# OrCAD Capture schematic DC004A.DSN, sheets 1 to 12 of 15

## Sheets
1 PAGE15 - HARDWARE: size B; title: ADC12DJ3200EVMCVAL (Hardware); rev: A; note: DC004
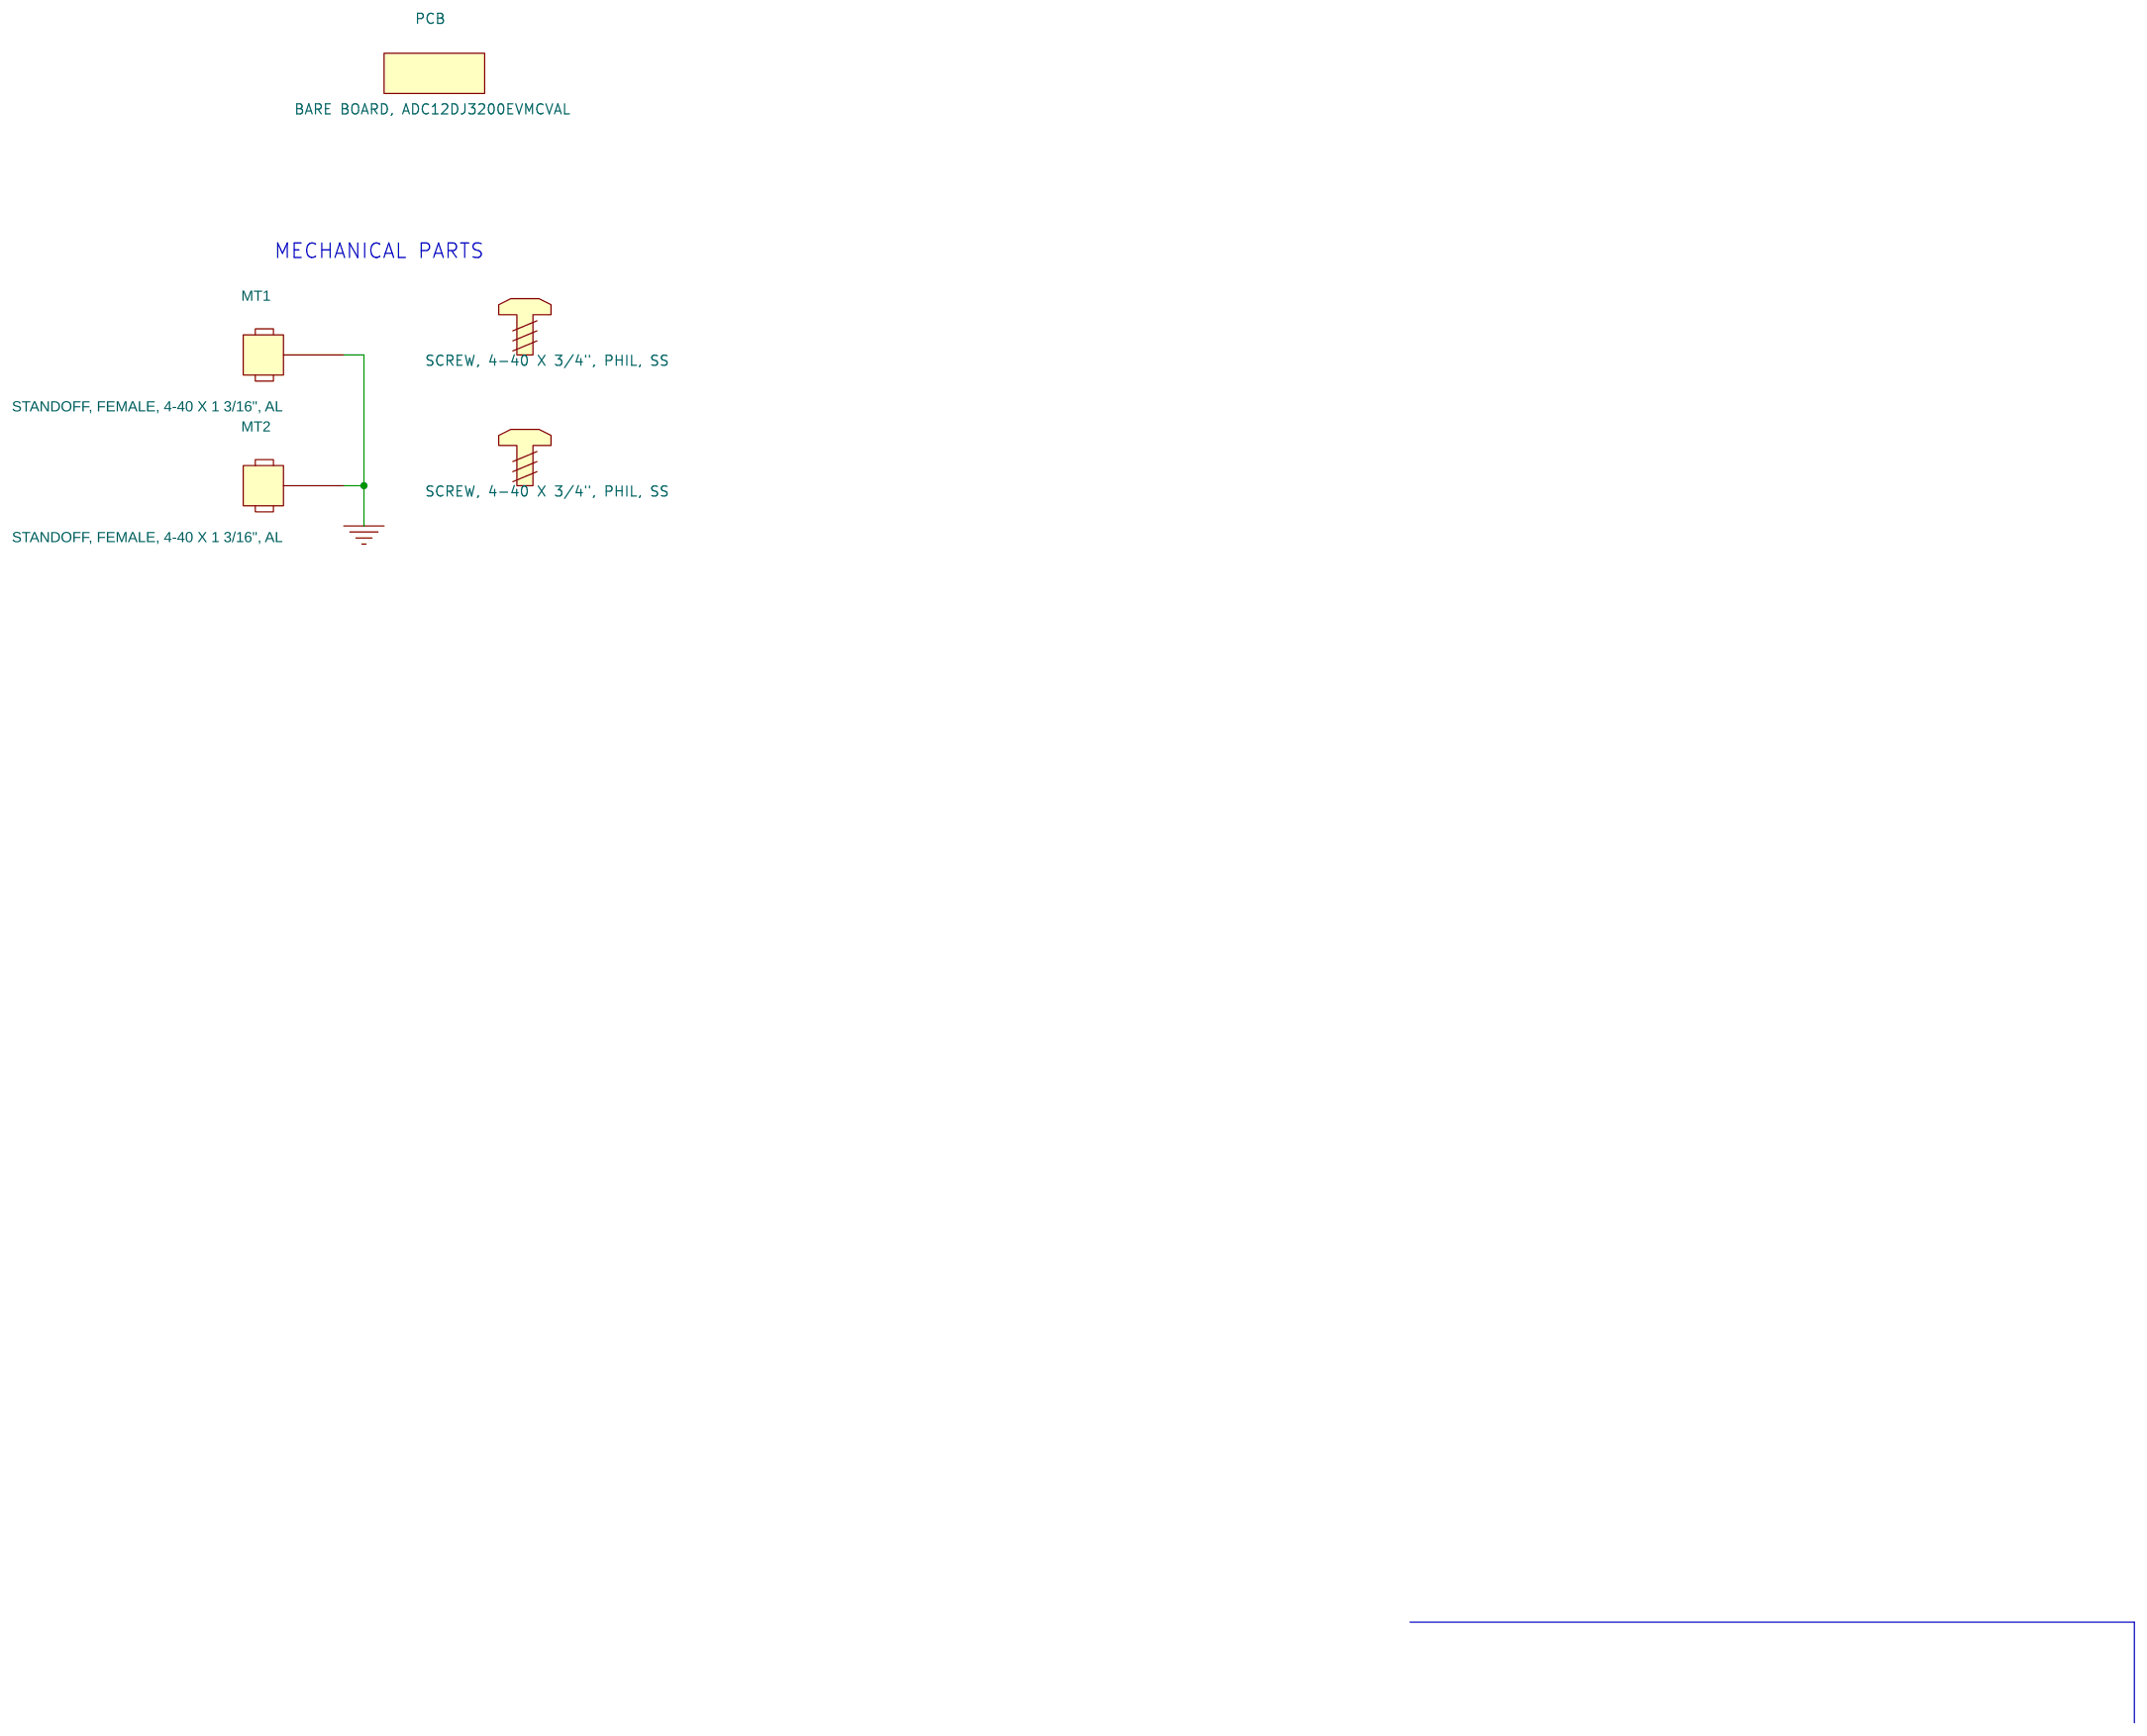
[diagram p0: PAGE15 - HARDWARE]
2 PAGE01 - BLOCK DIAGRAM: title: ADC12DJ3200EVMCVAL
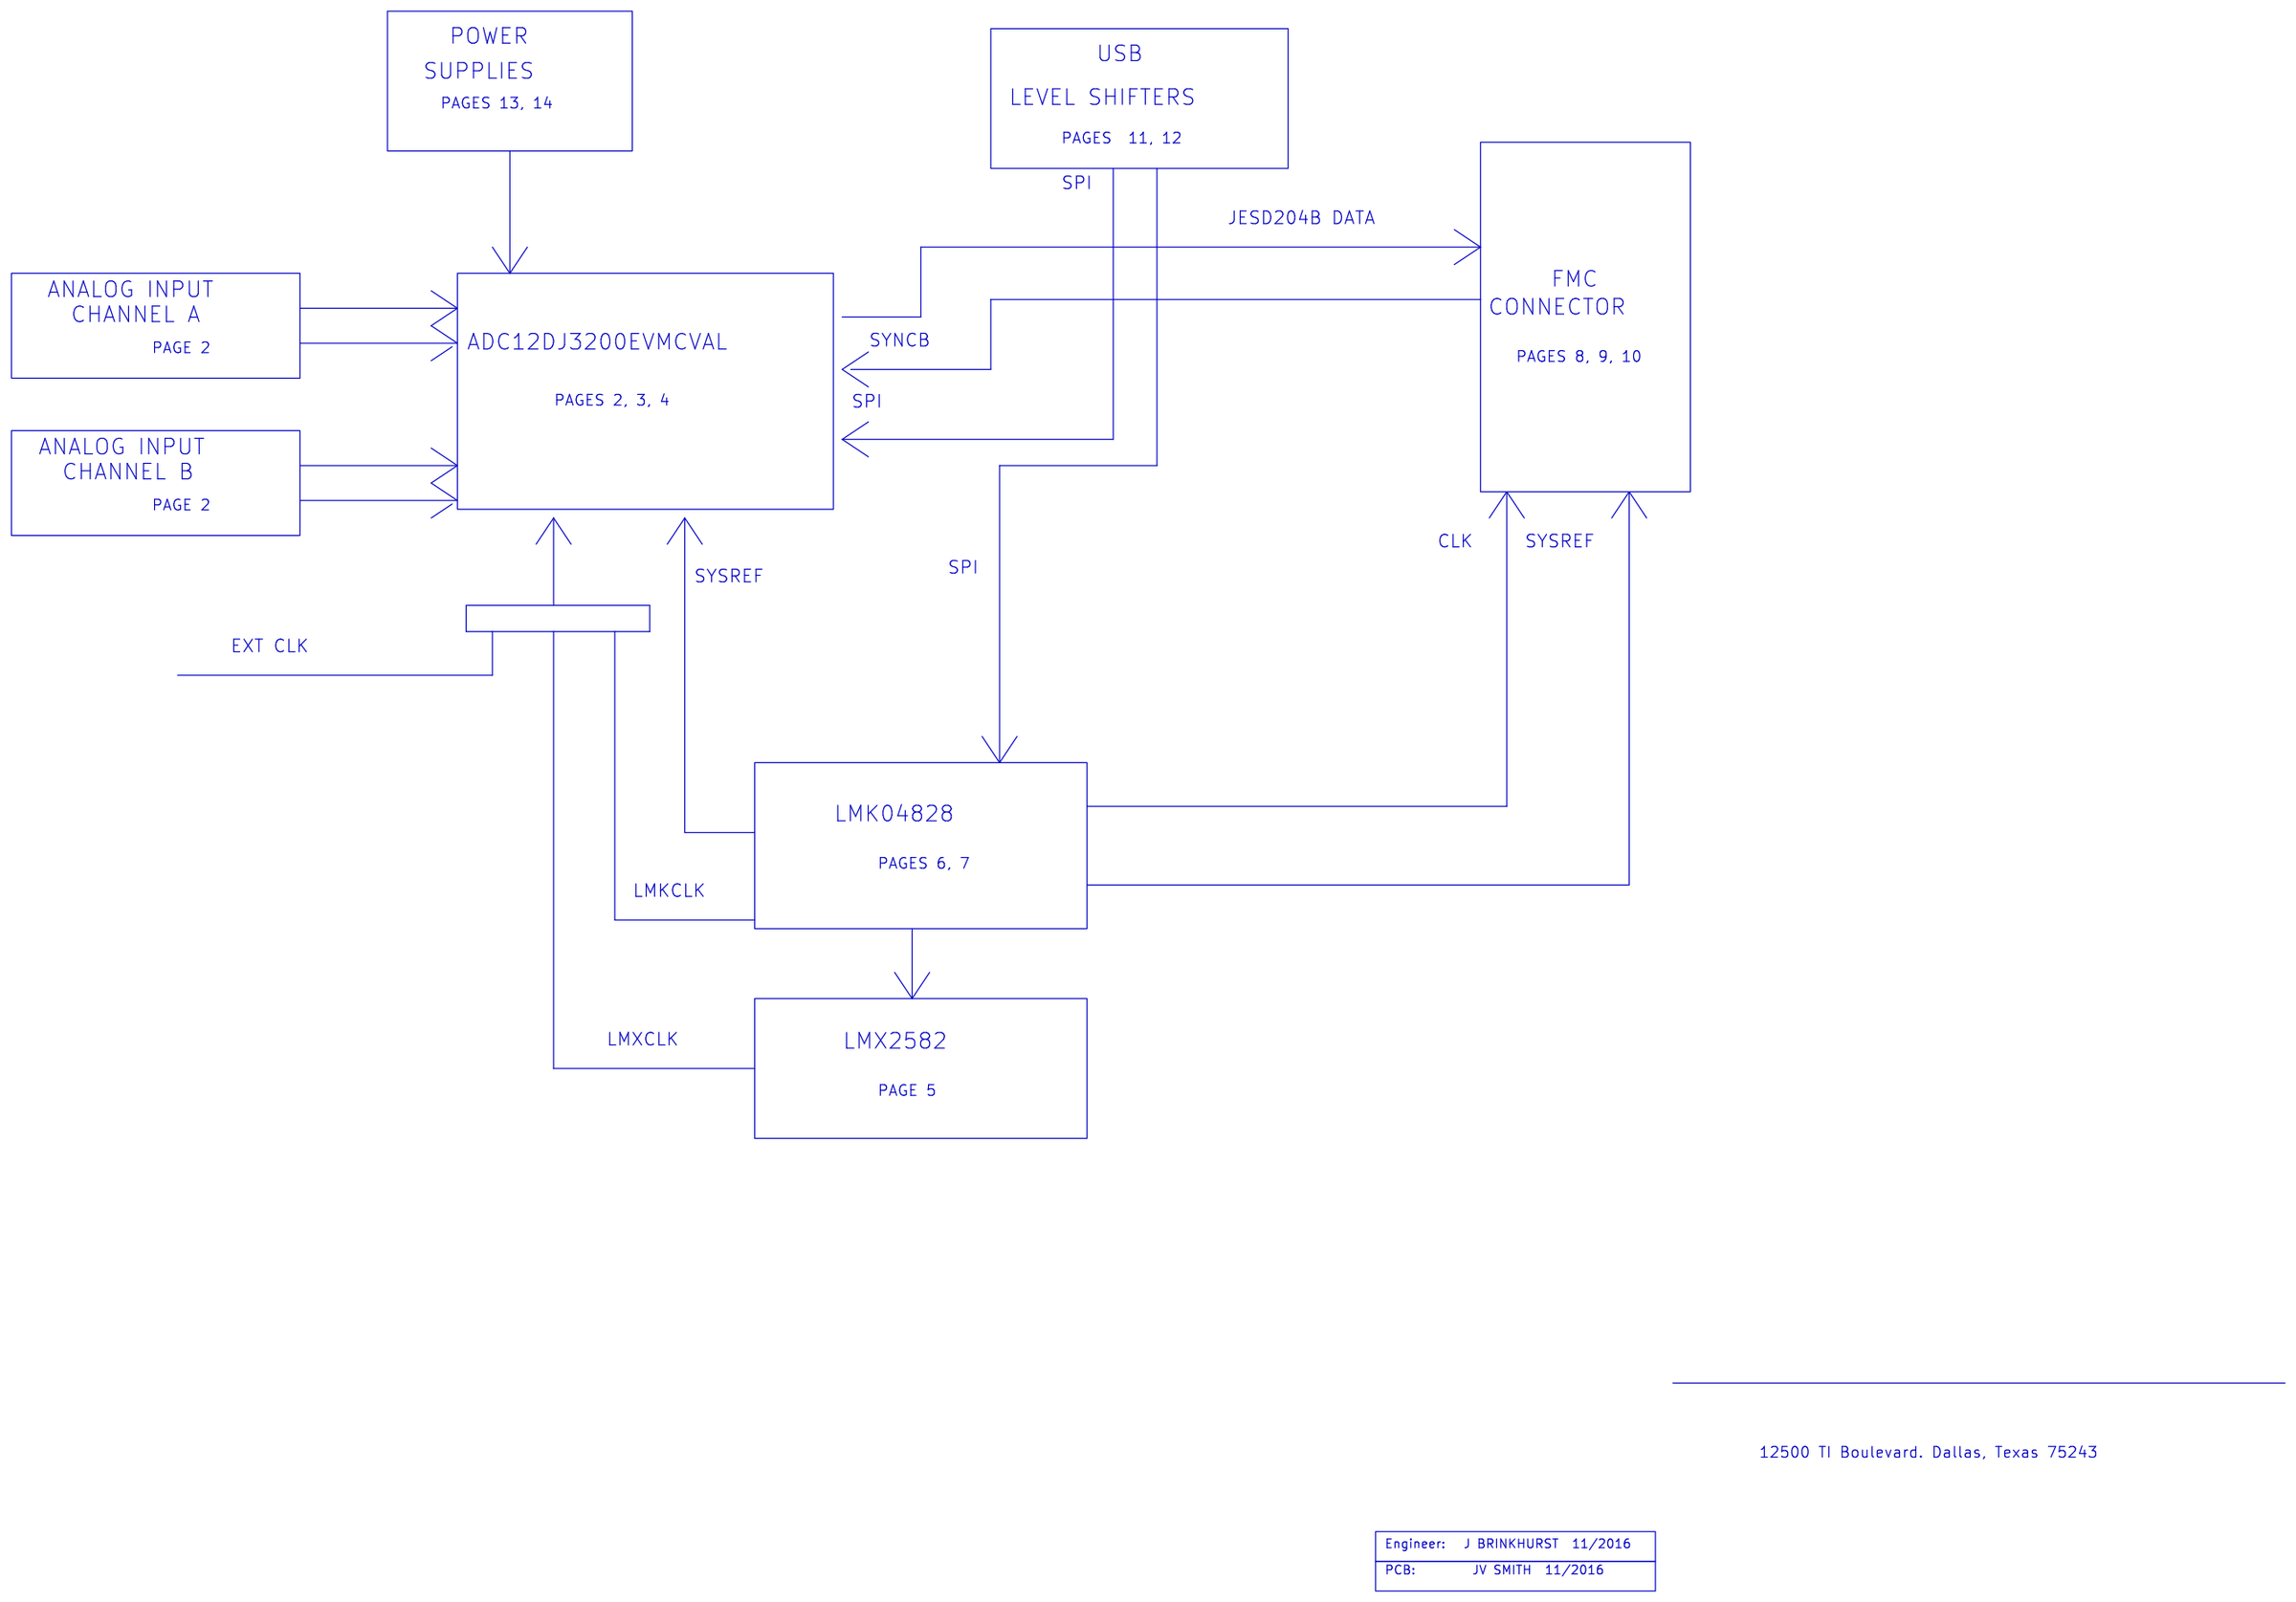
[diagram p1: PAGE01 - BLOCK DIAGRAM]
3 PAGE02 - ADC ANALOG INPUT: size B; title: ADC12DJ3200EVMCVAL (ANALOG INPUT)
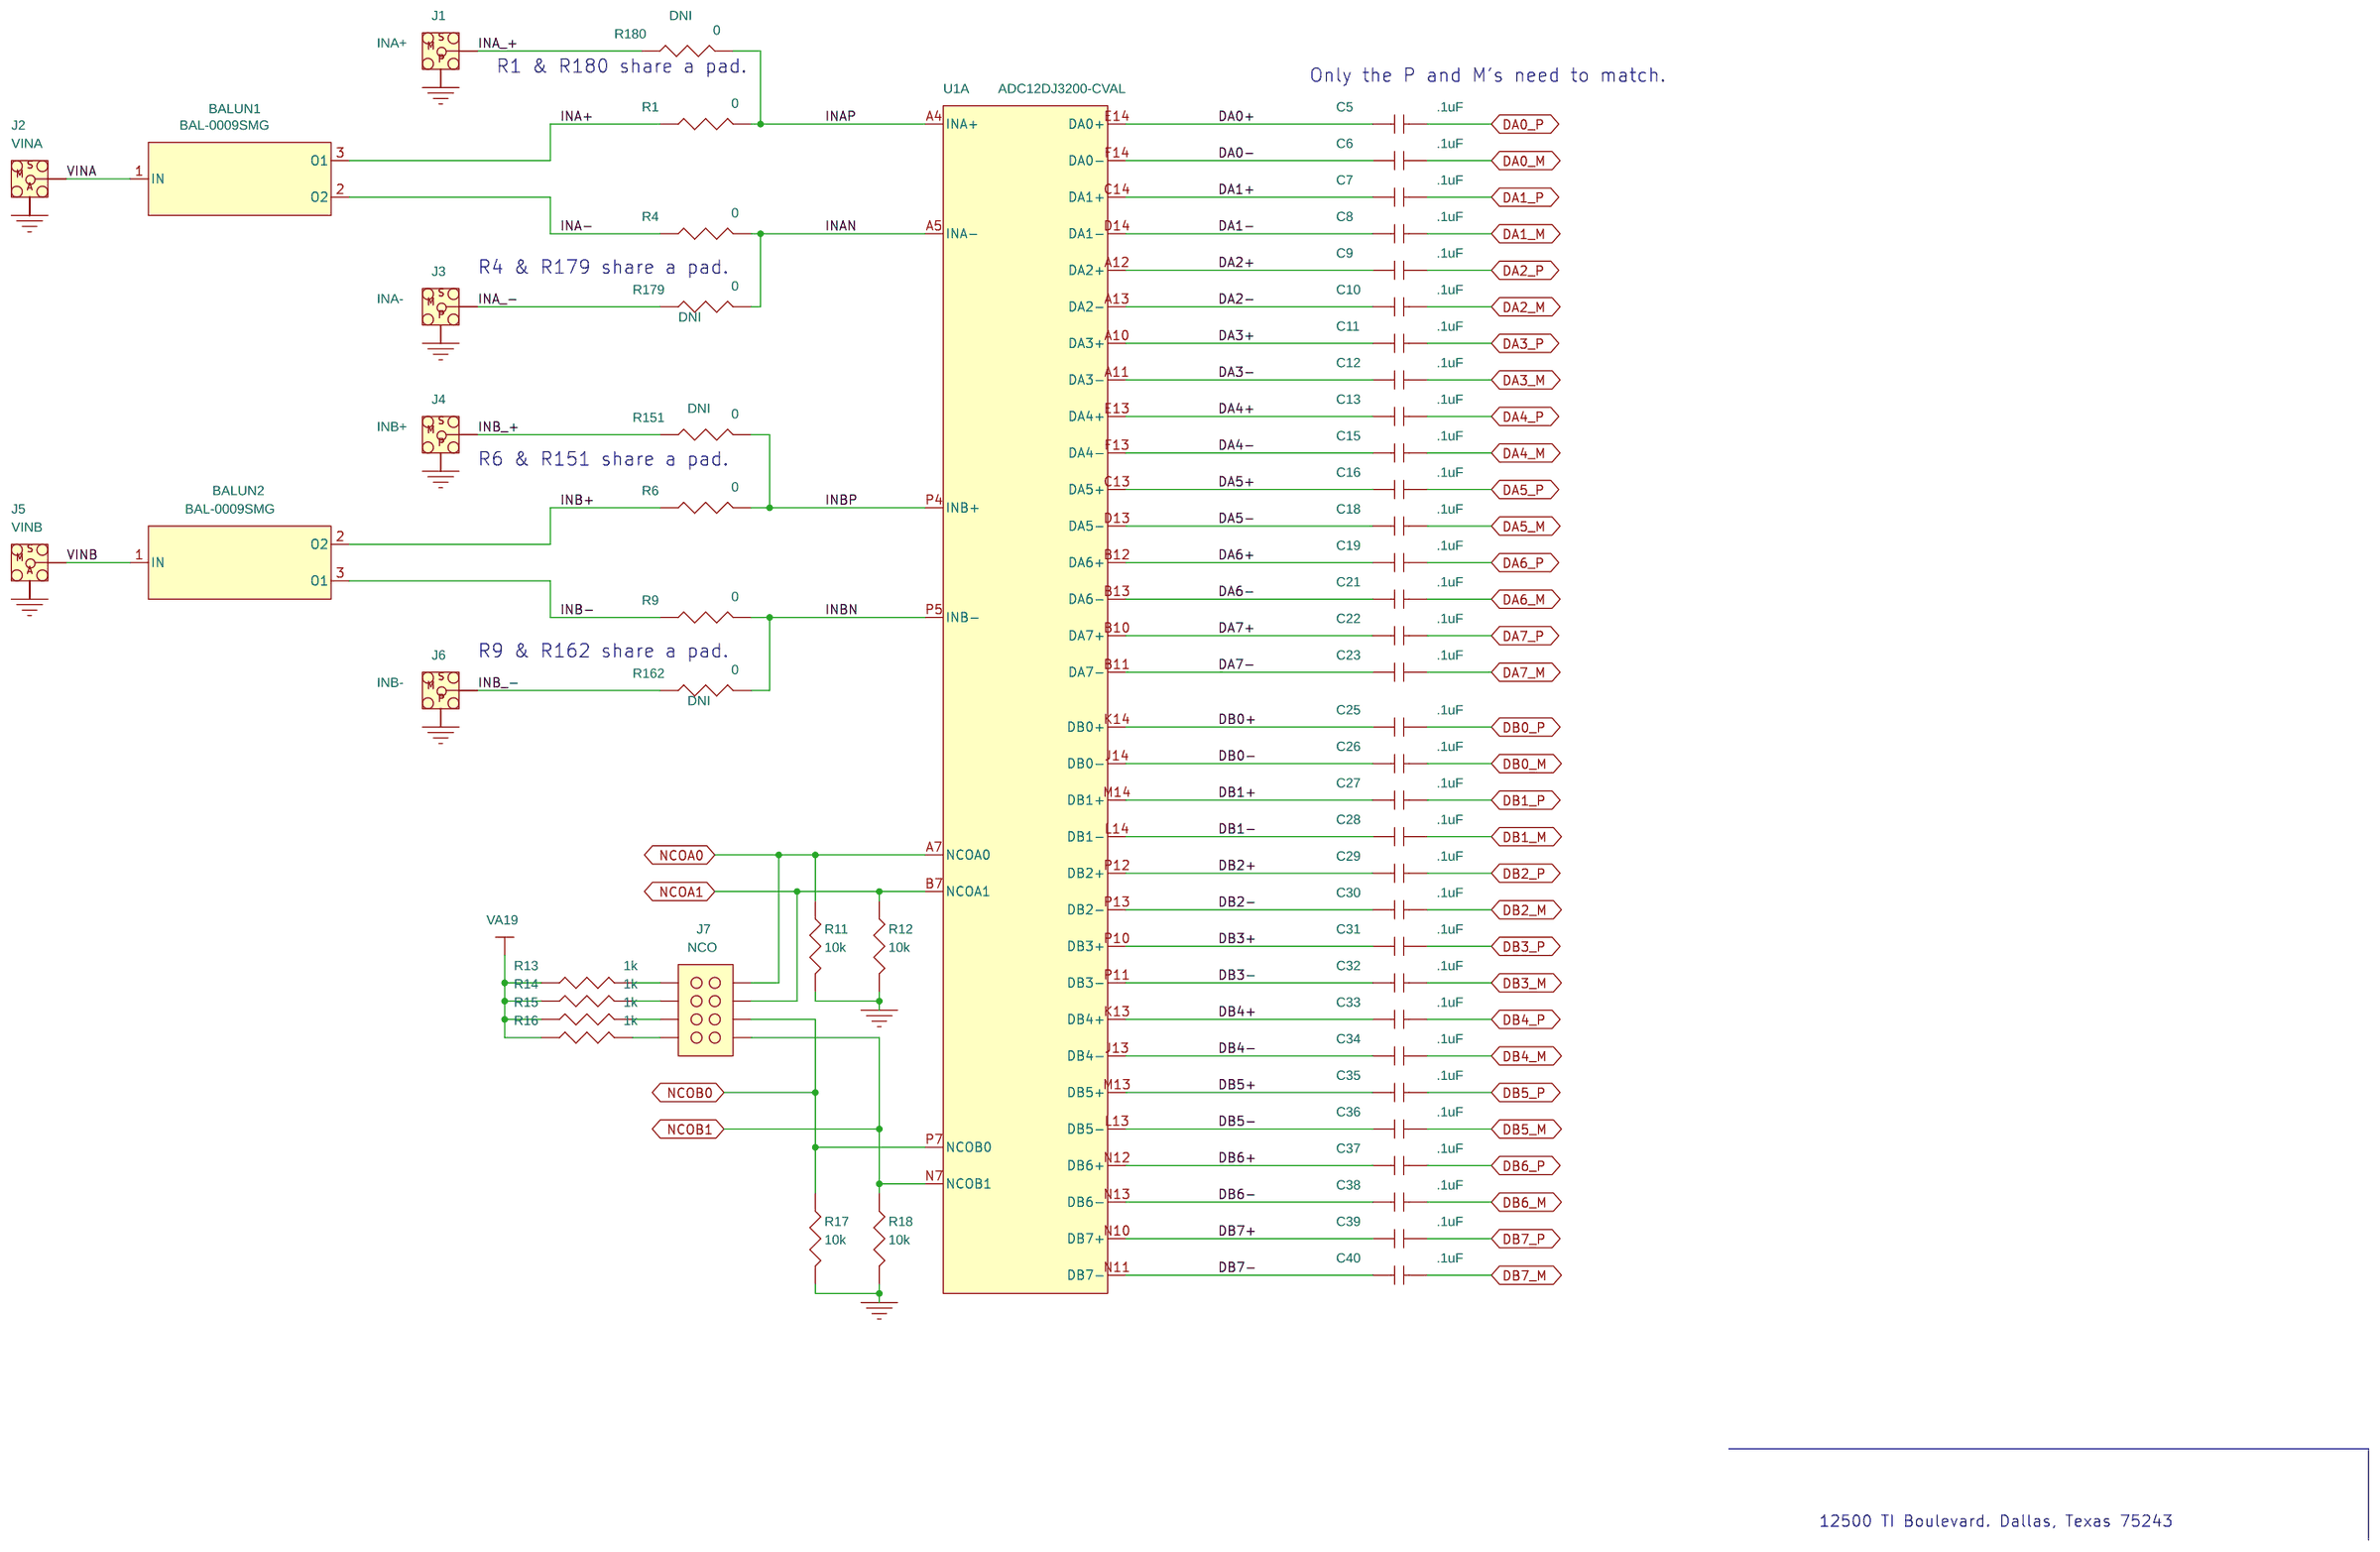
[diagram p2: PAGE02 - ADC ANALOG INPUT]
4 PAGE03 - ADC SPI: size B; title: ADC12DJ3200EVMCVAL (ADC SPI)
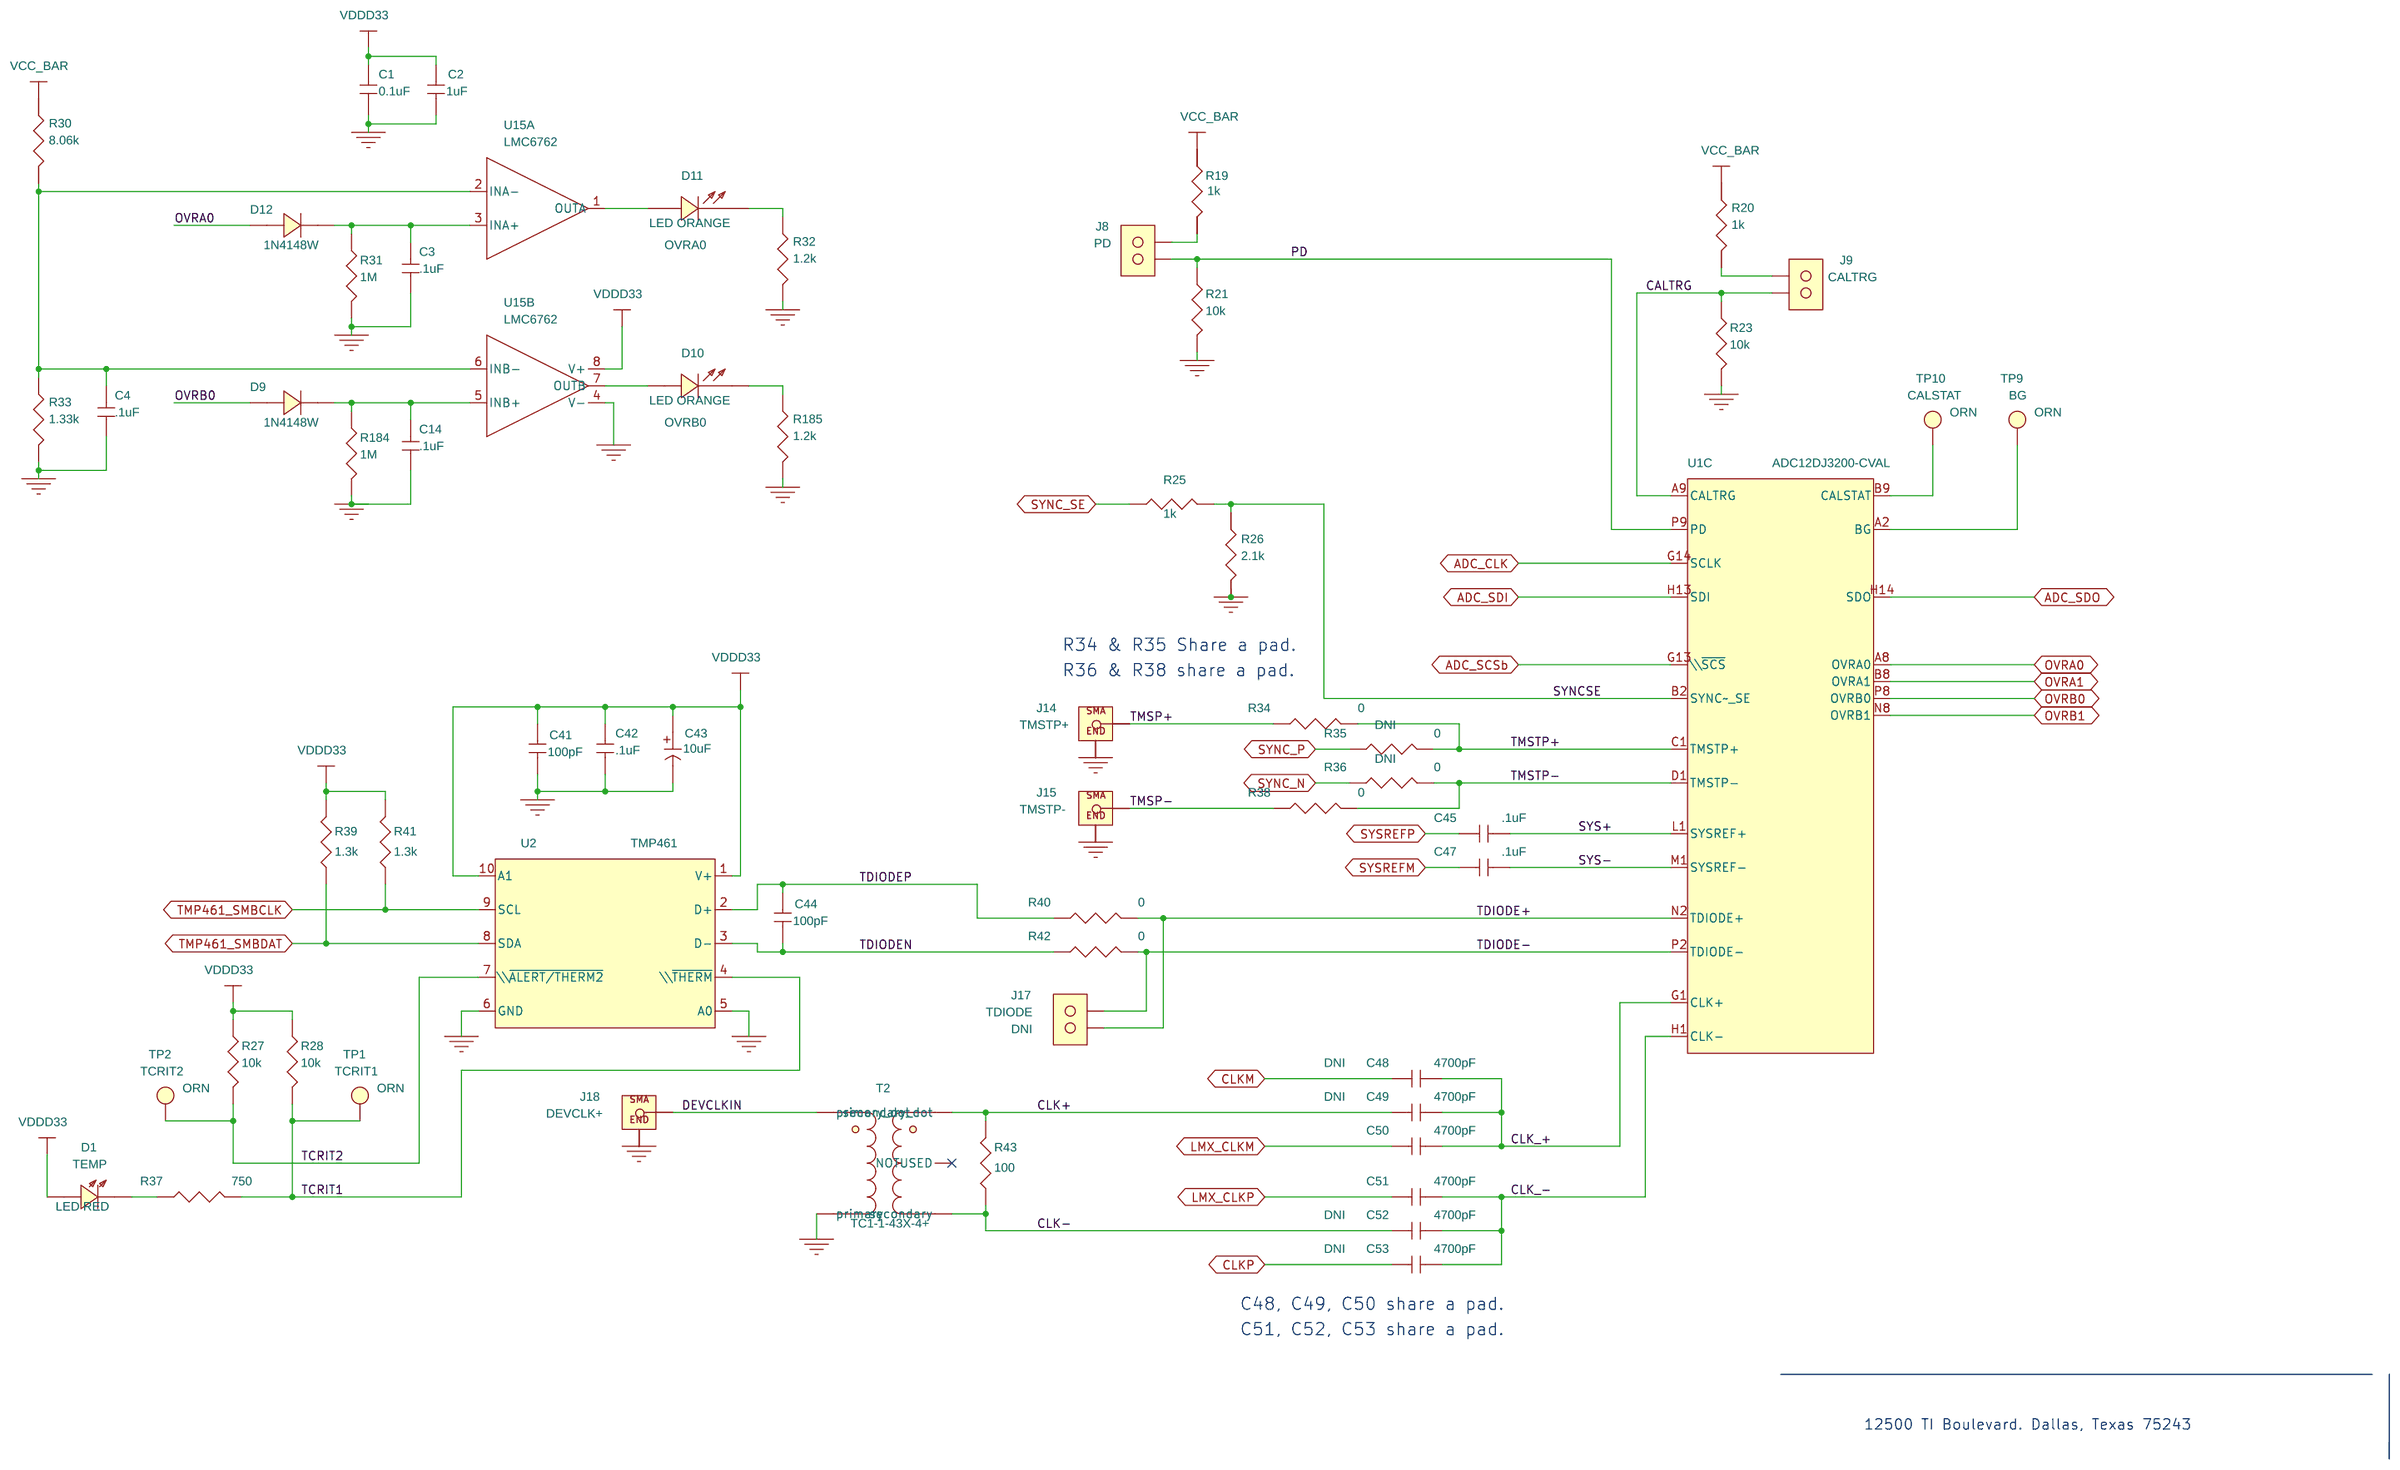
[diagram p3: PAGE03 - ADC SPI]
5 PAGE04 - ADC PWR: size B; title: ADC12DJ3200EVMCVAL (ADC PWR)
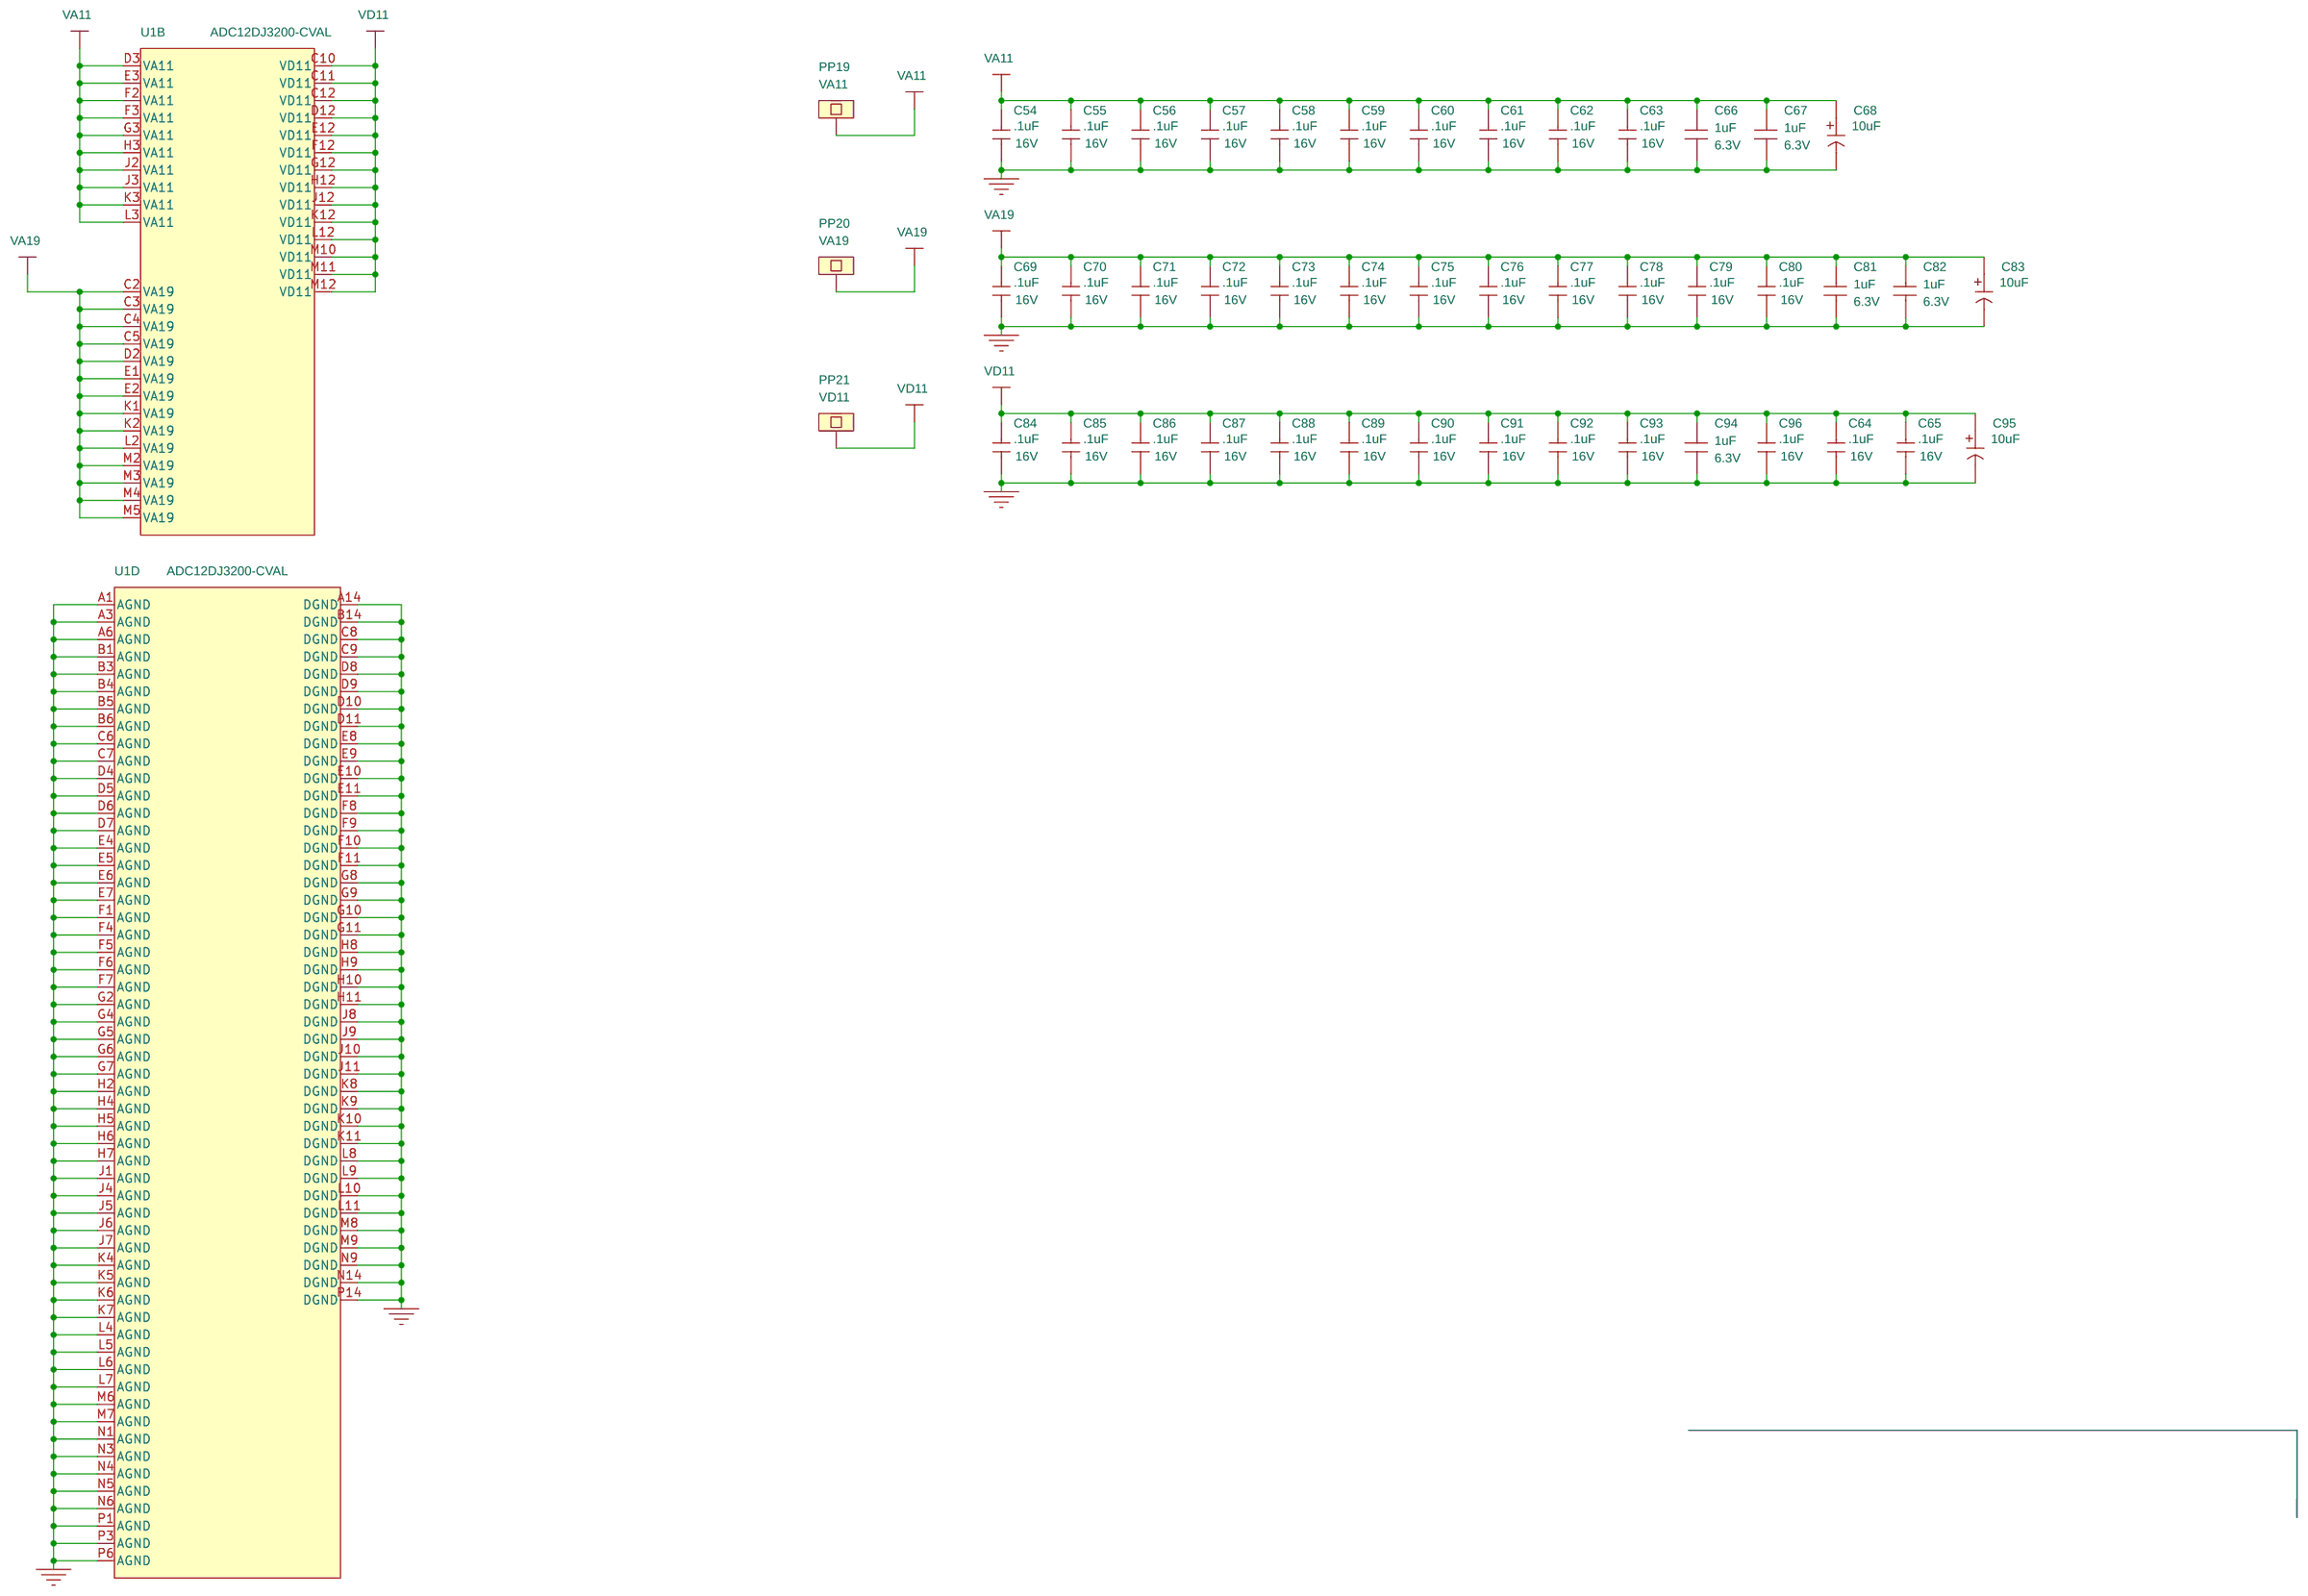
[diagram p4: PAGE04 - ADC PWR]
6 PAGE05 - LMX: size B; title: ADC12DJ3200EVMCVAL (LMX)
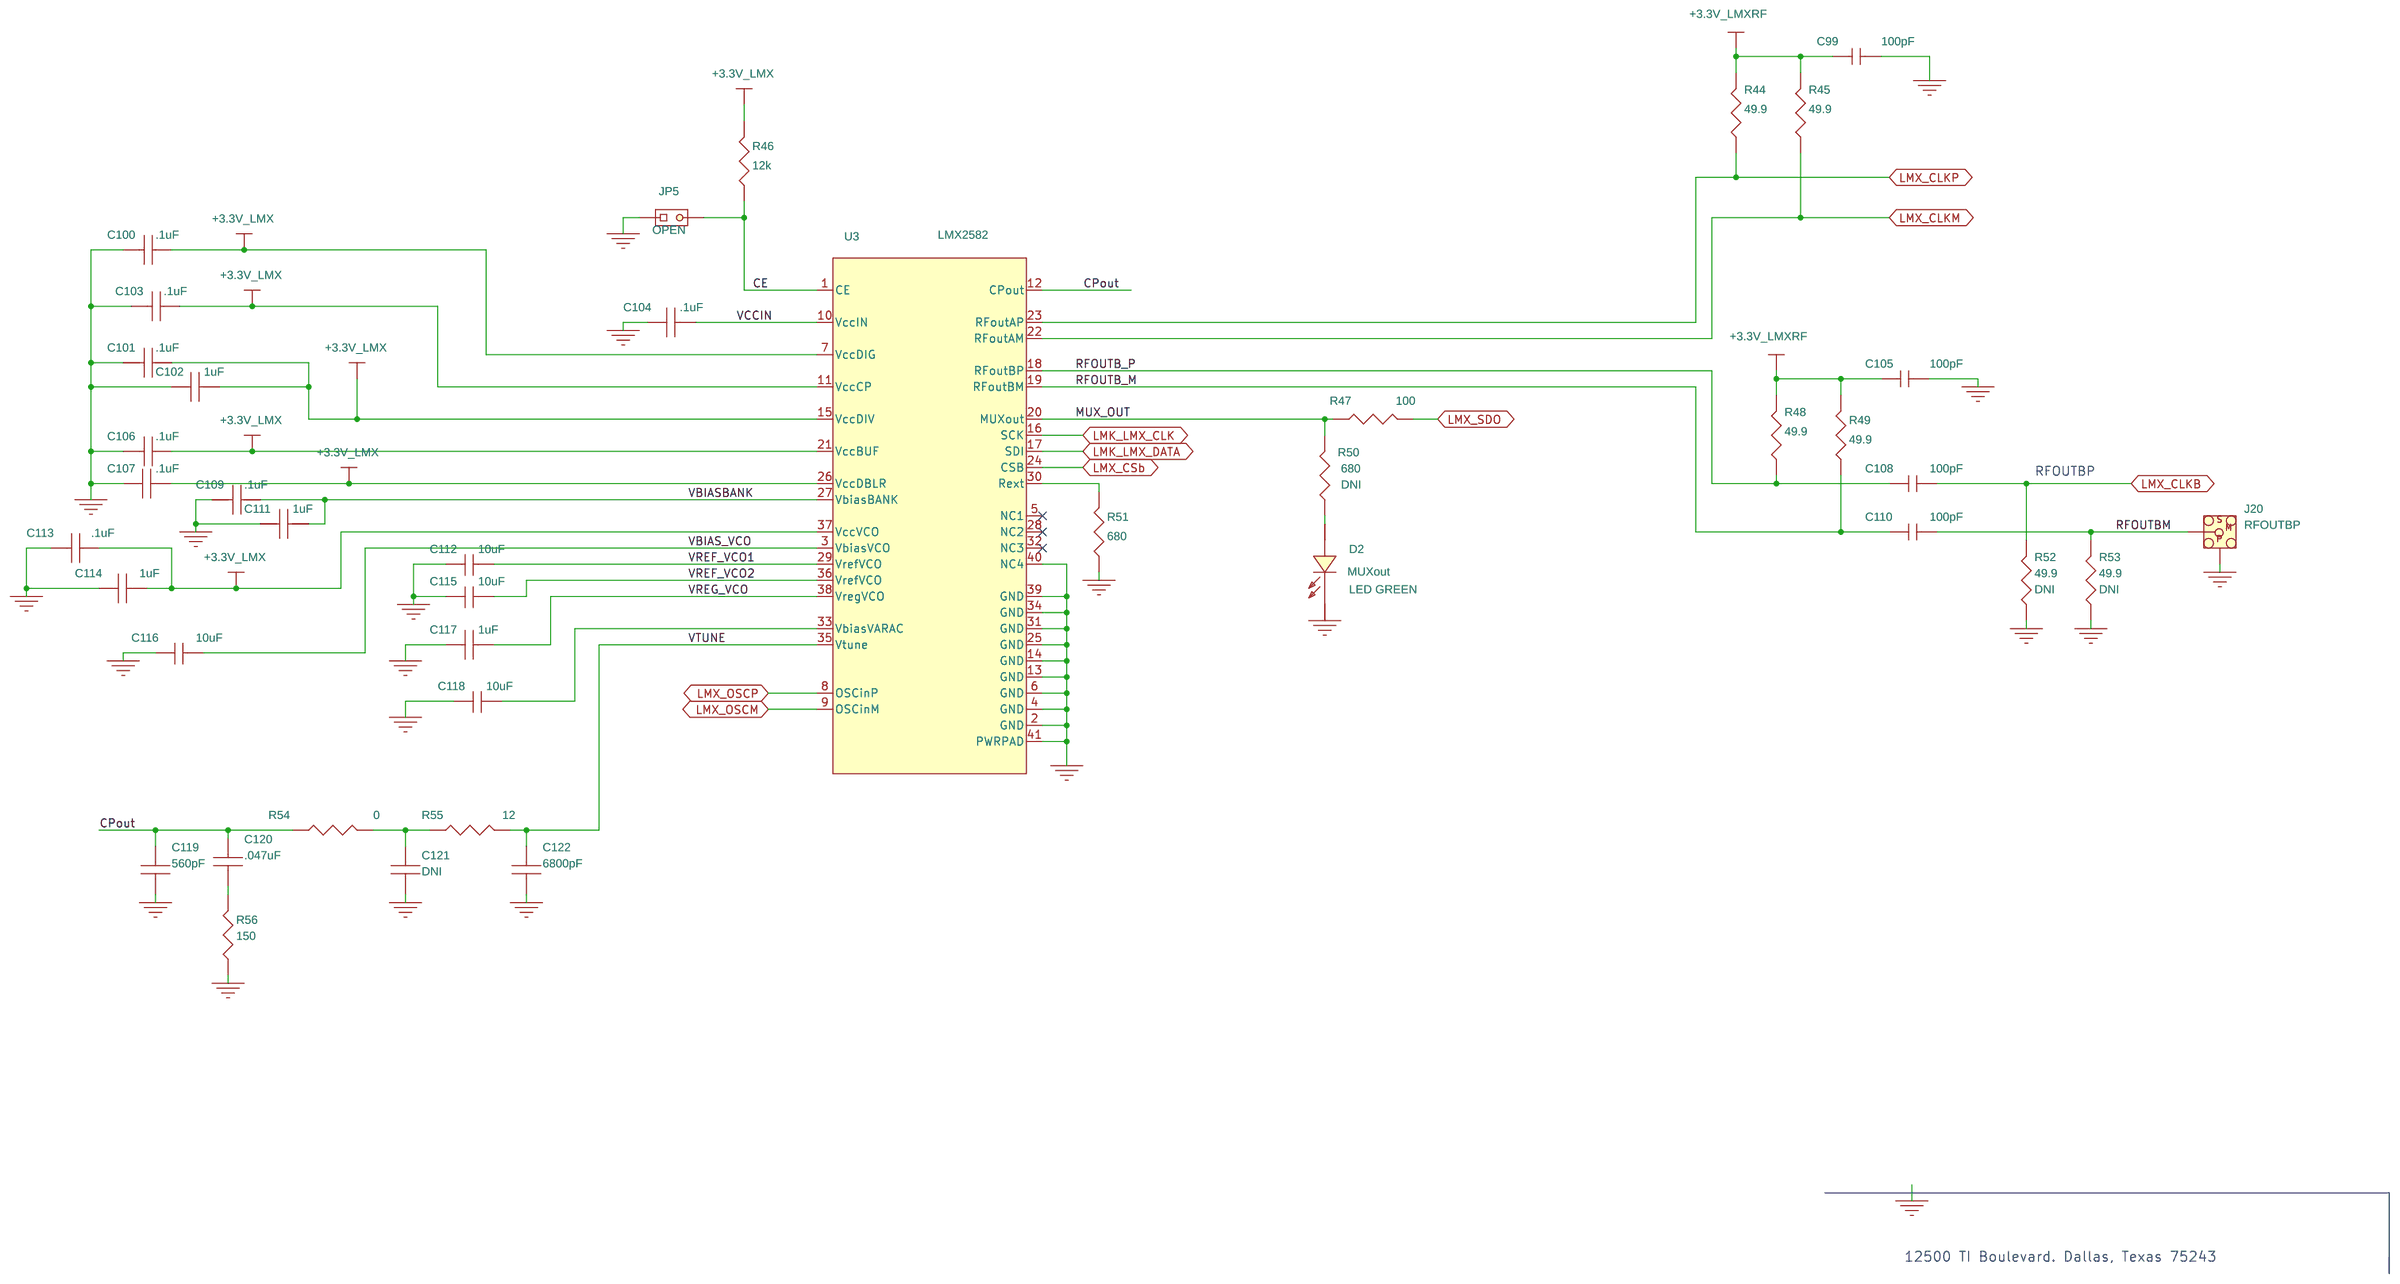
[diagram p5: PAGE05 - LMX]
7 PAGE06 - LMK: size B; title: ADC12DJ3200EVMCVAL (LMK)
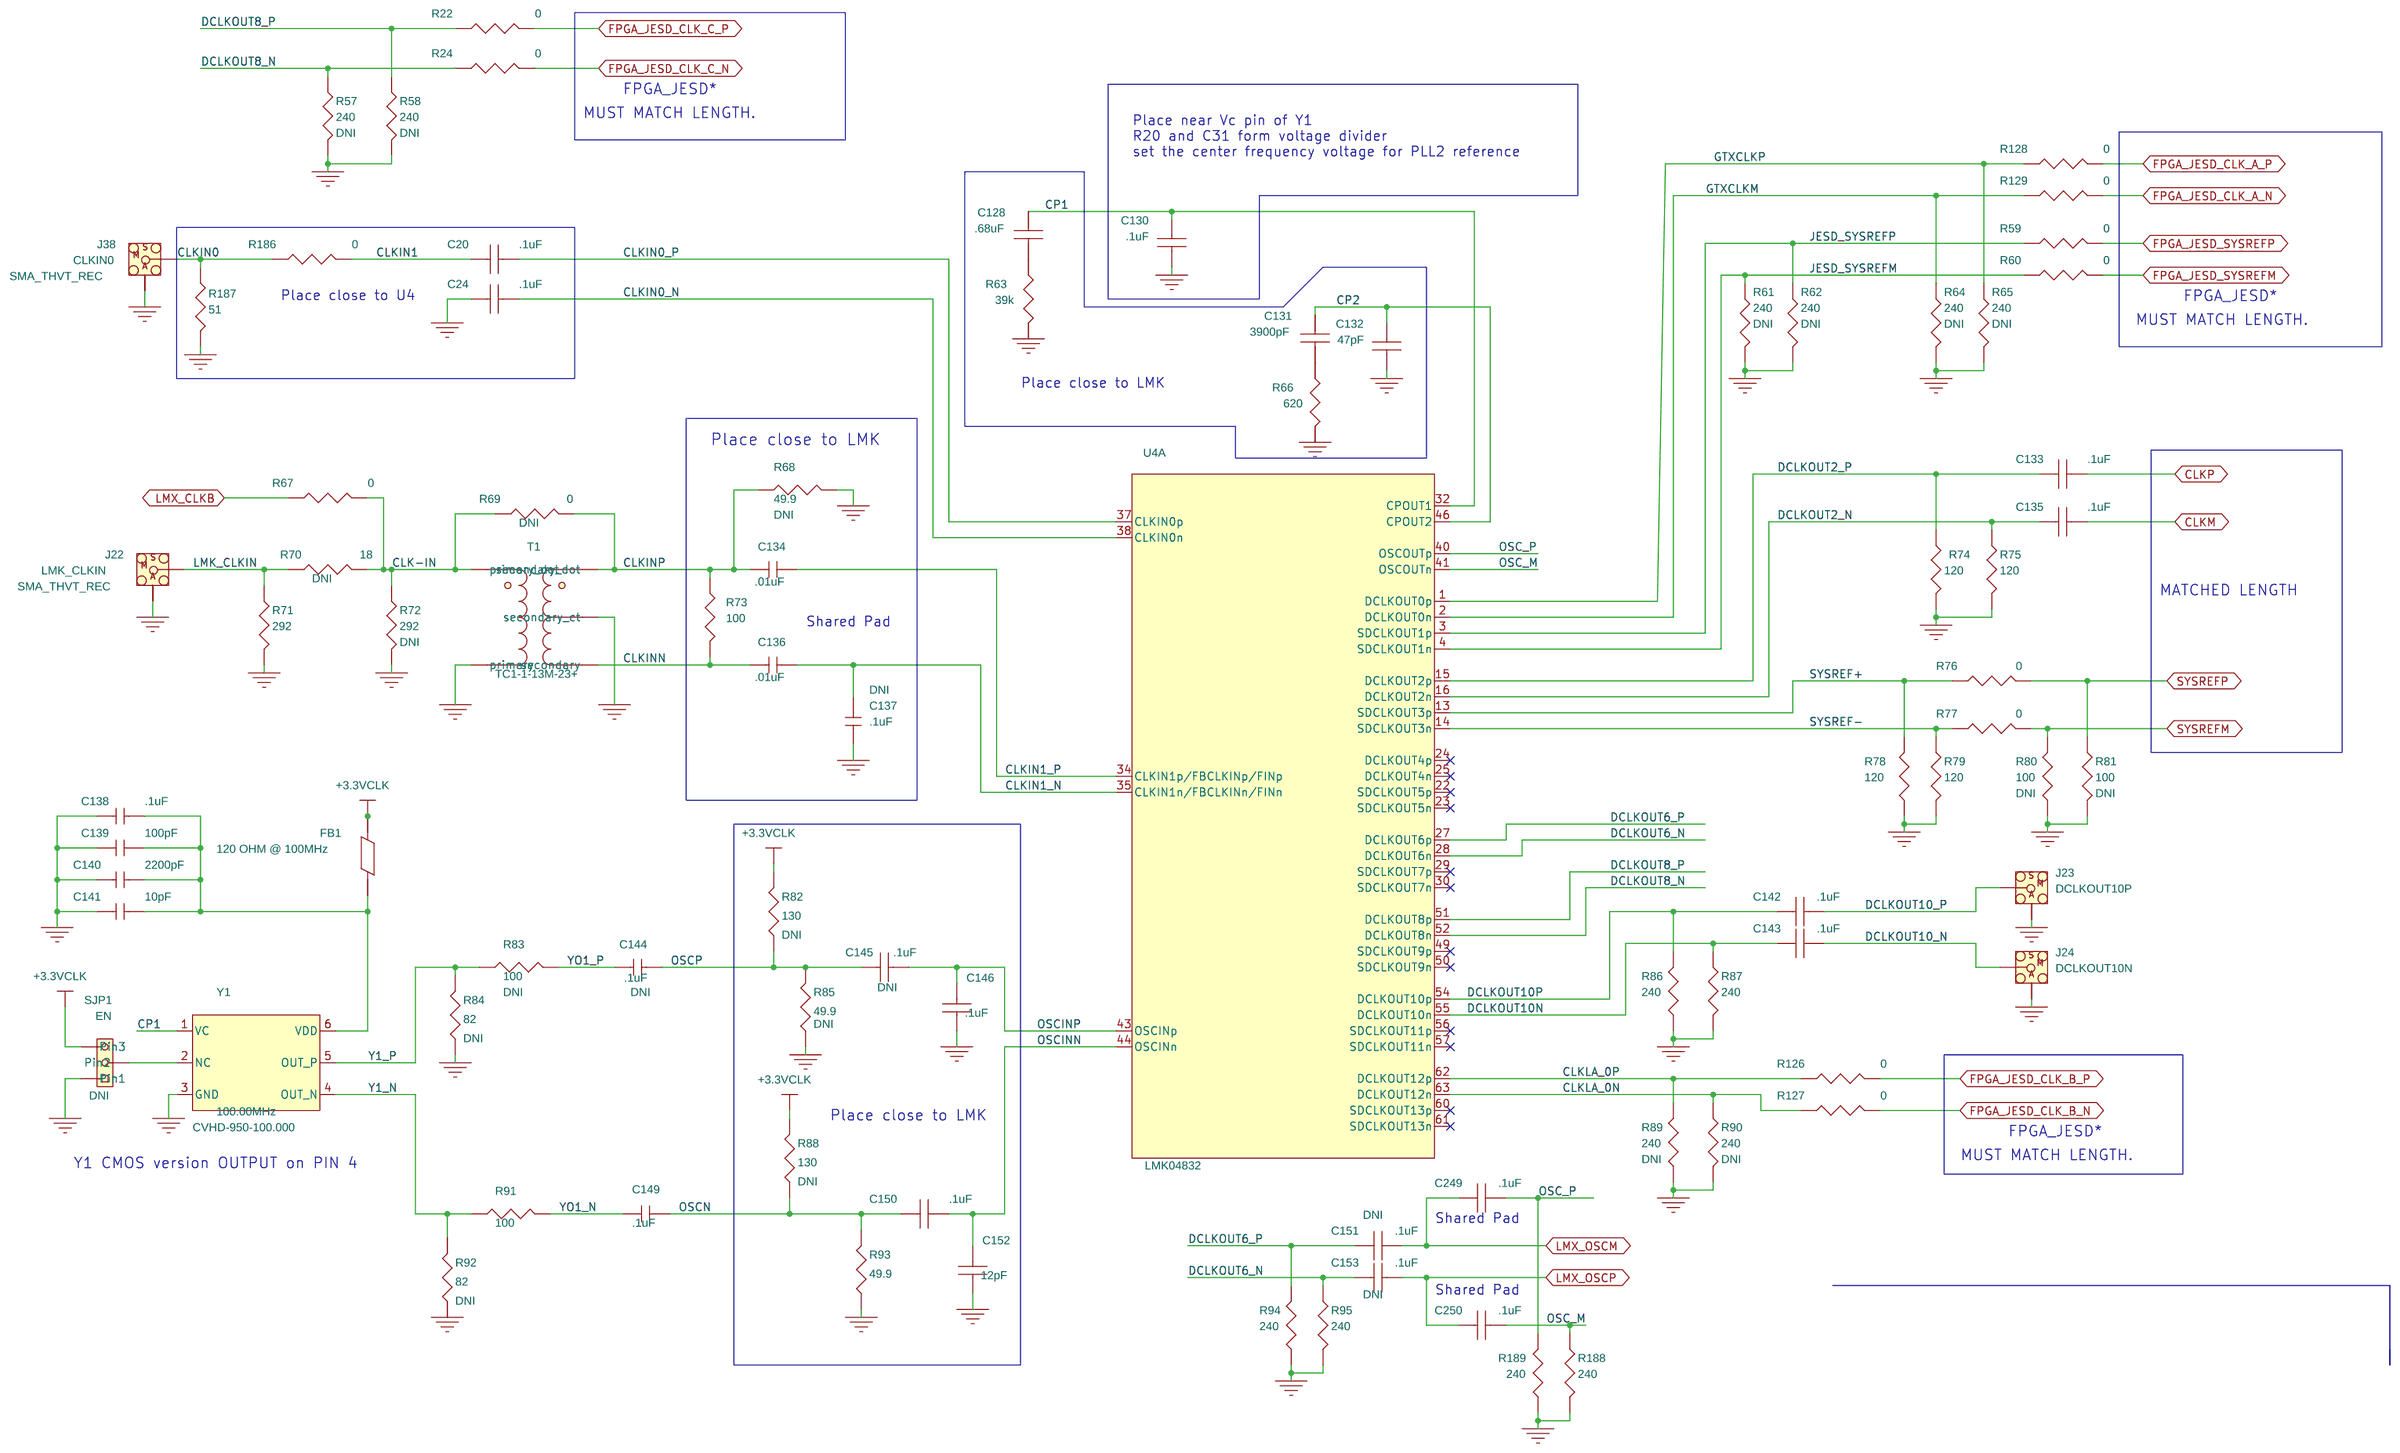
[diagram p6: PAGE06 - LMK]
8 PAGE07 - LMK POWER: size B; title: ADC12DJ3200EVMCVAL (LMK PWR)
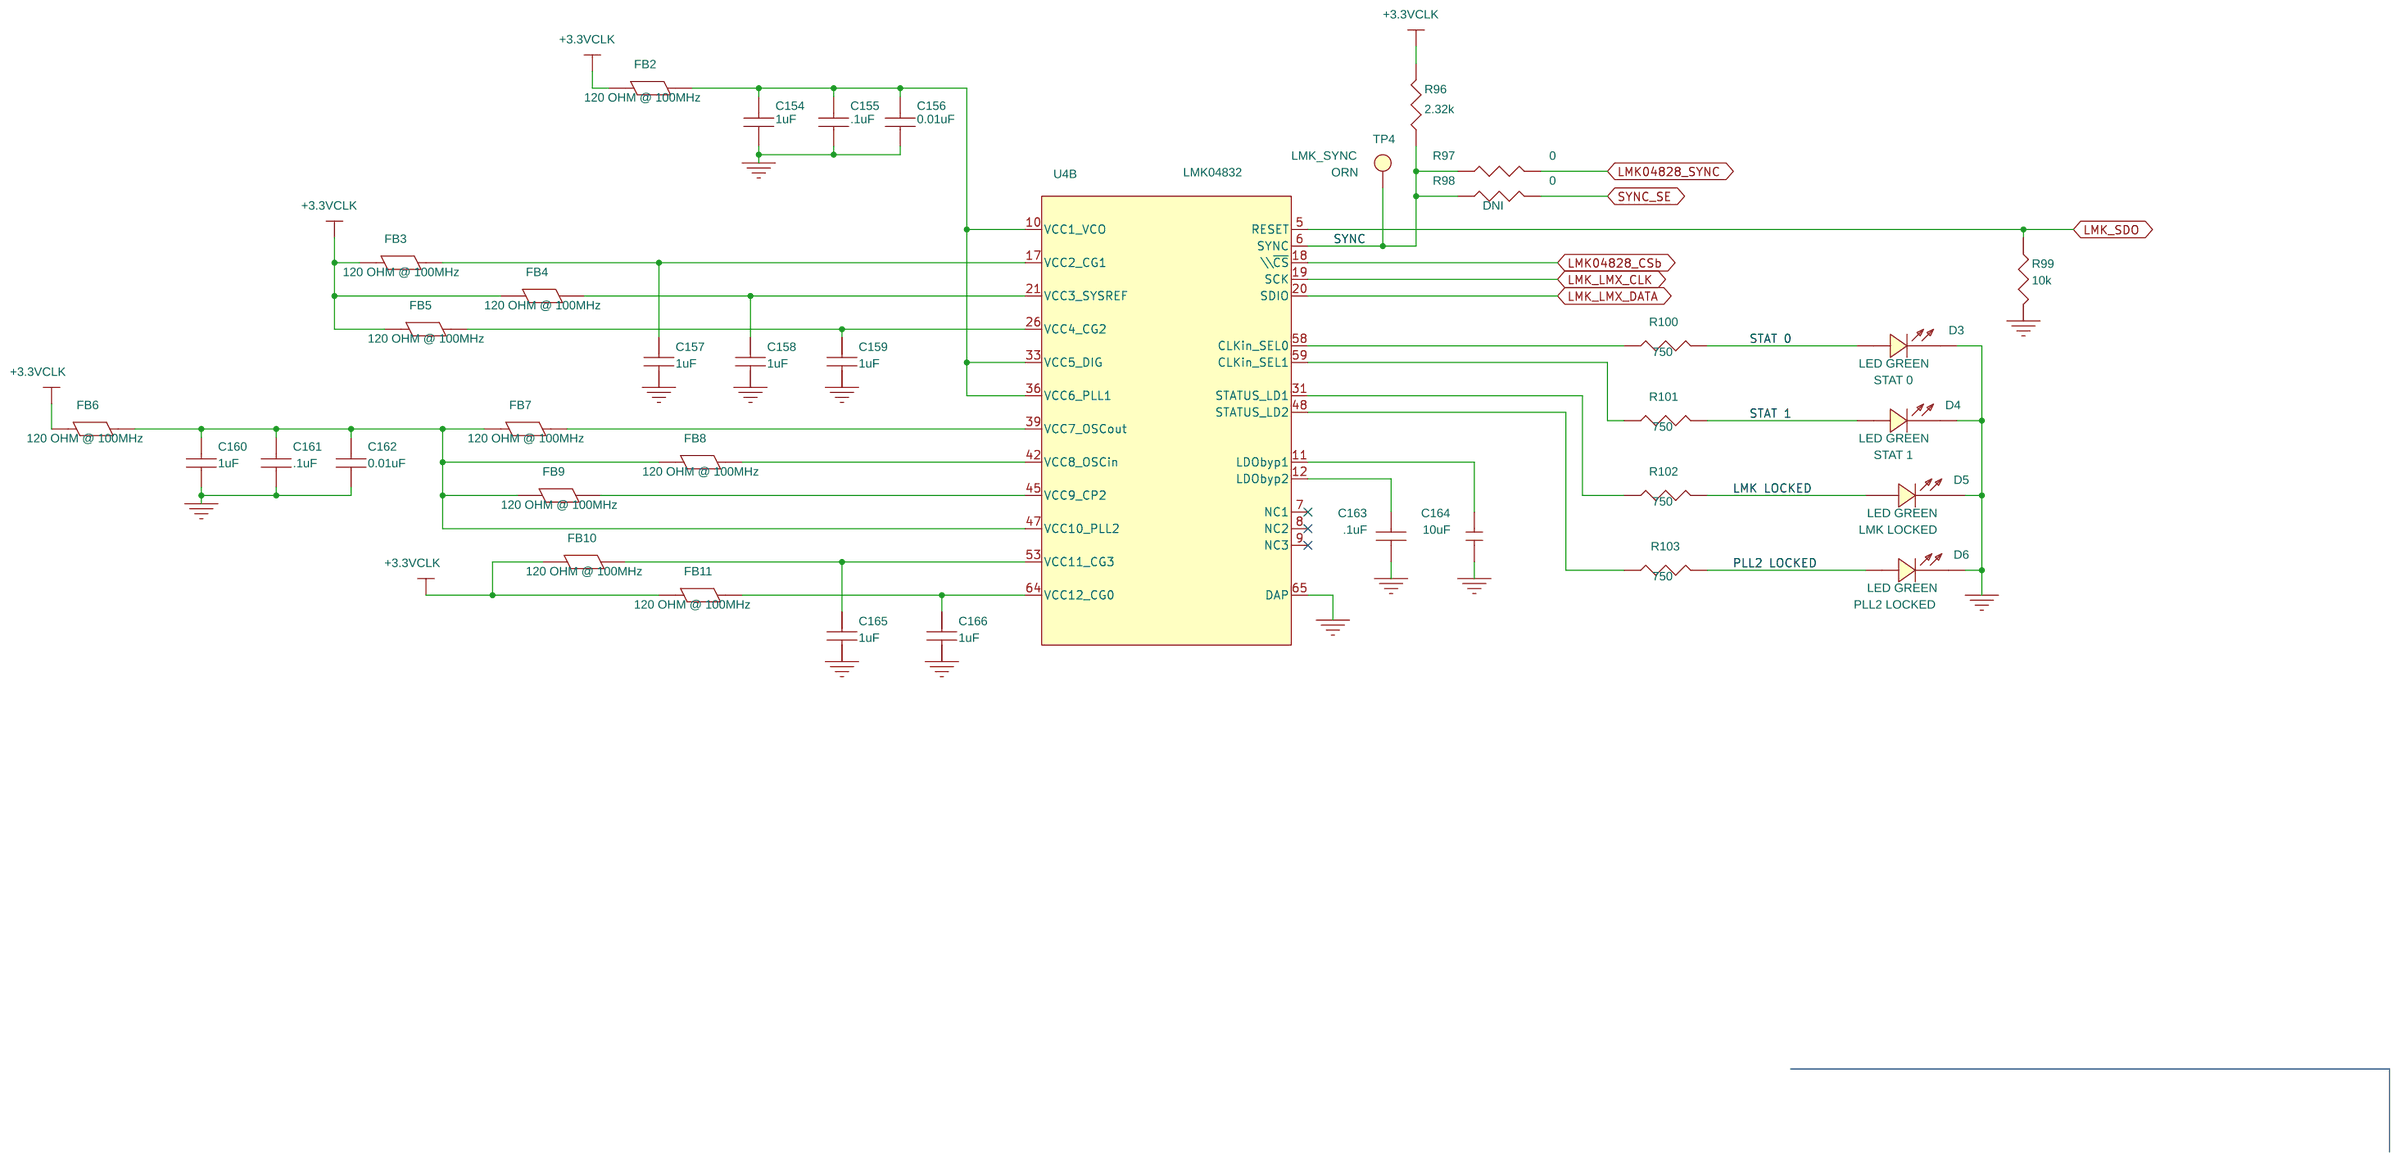
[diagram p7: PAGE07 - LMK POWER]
9 PAGE08 - OUTPUT FMC CONN: size B; title: ADC12DJ3200EVMCVAL (FMC)
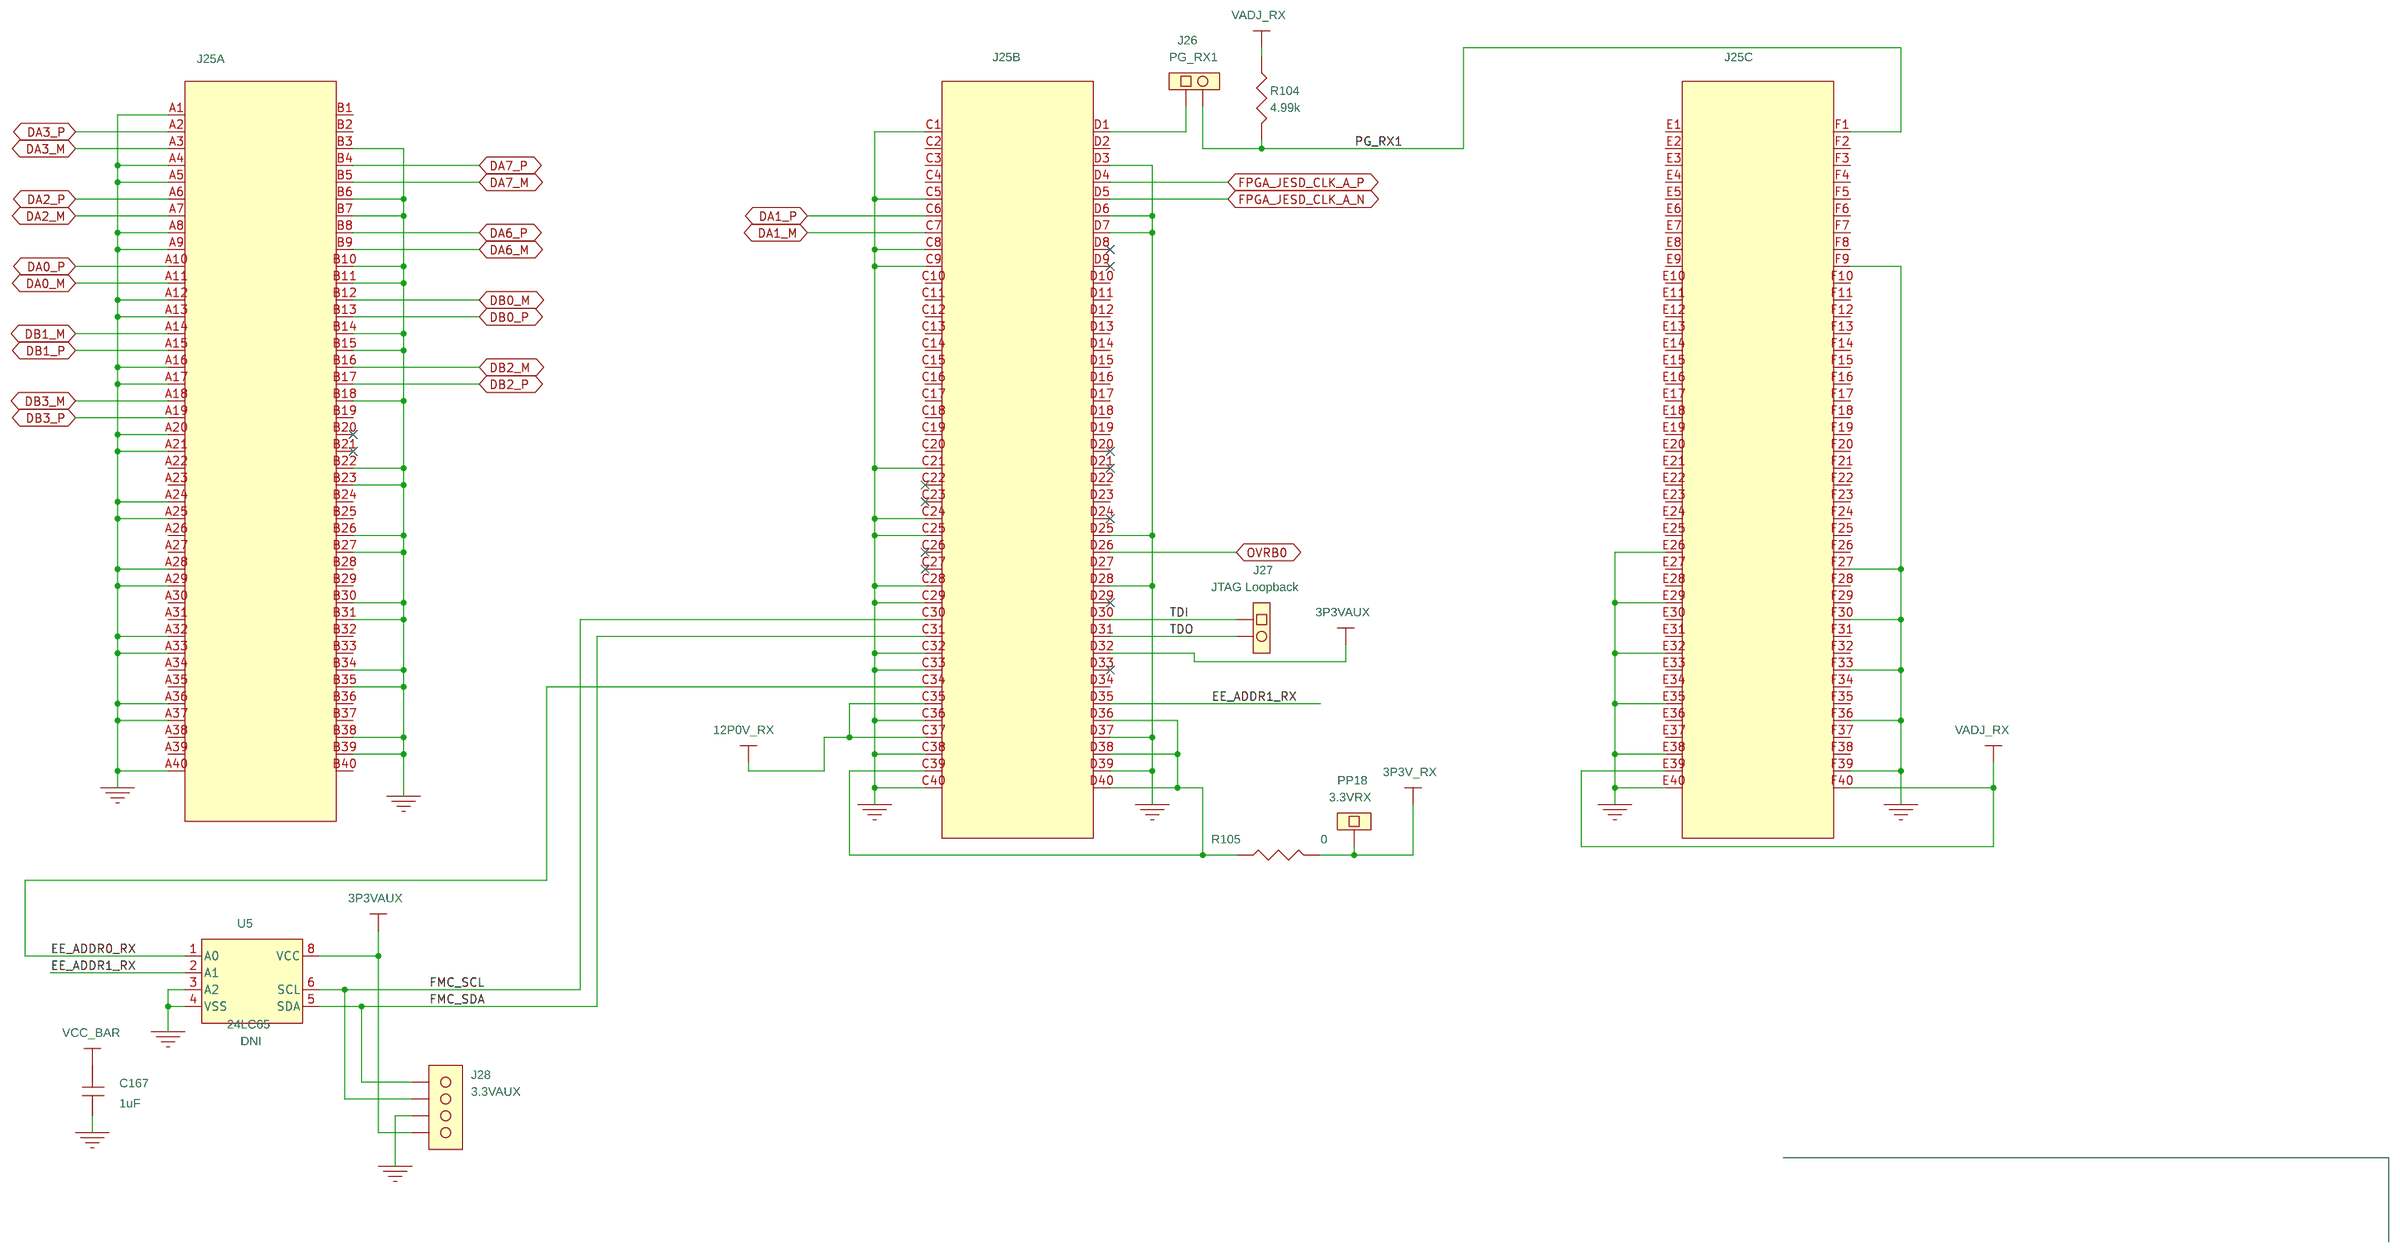
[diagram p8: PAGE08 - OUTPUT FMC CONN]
10 PAGE09 - OUTPUT FMC CONN: size B; title: ADC12DJ3200EVMCVAL (FMC)
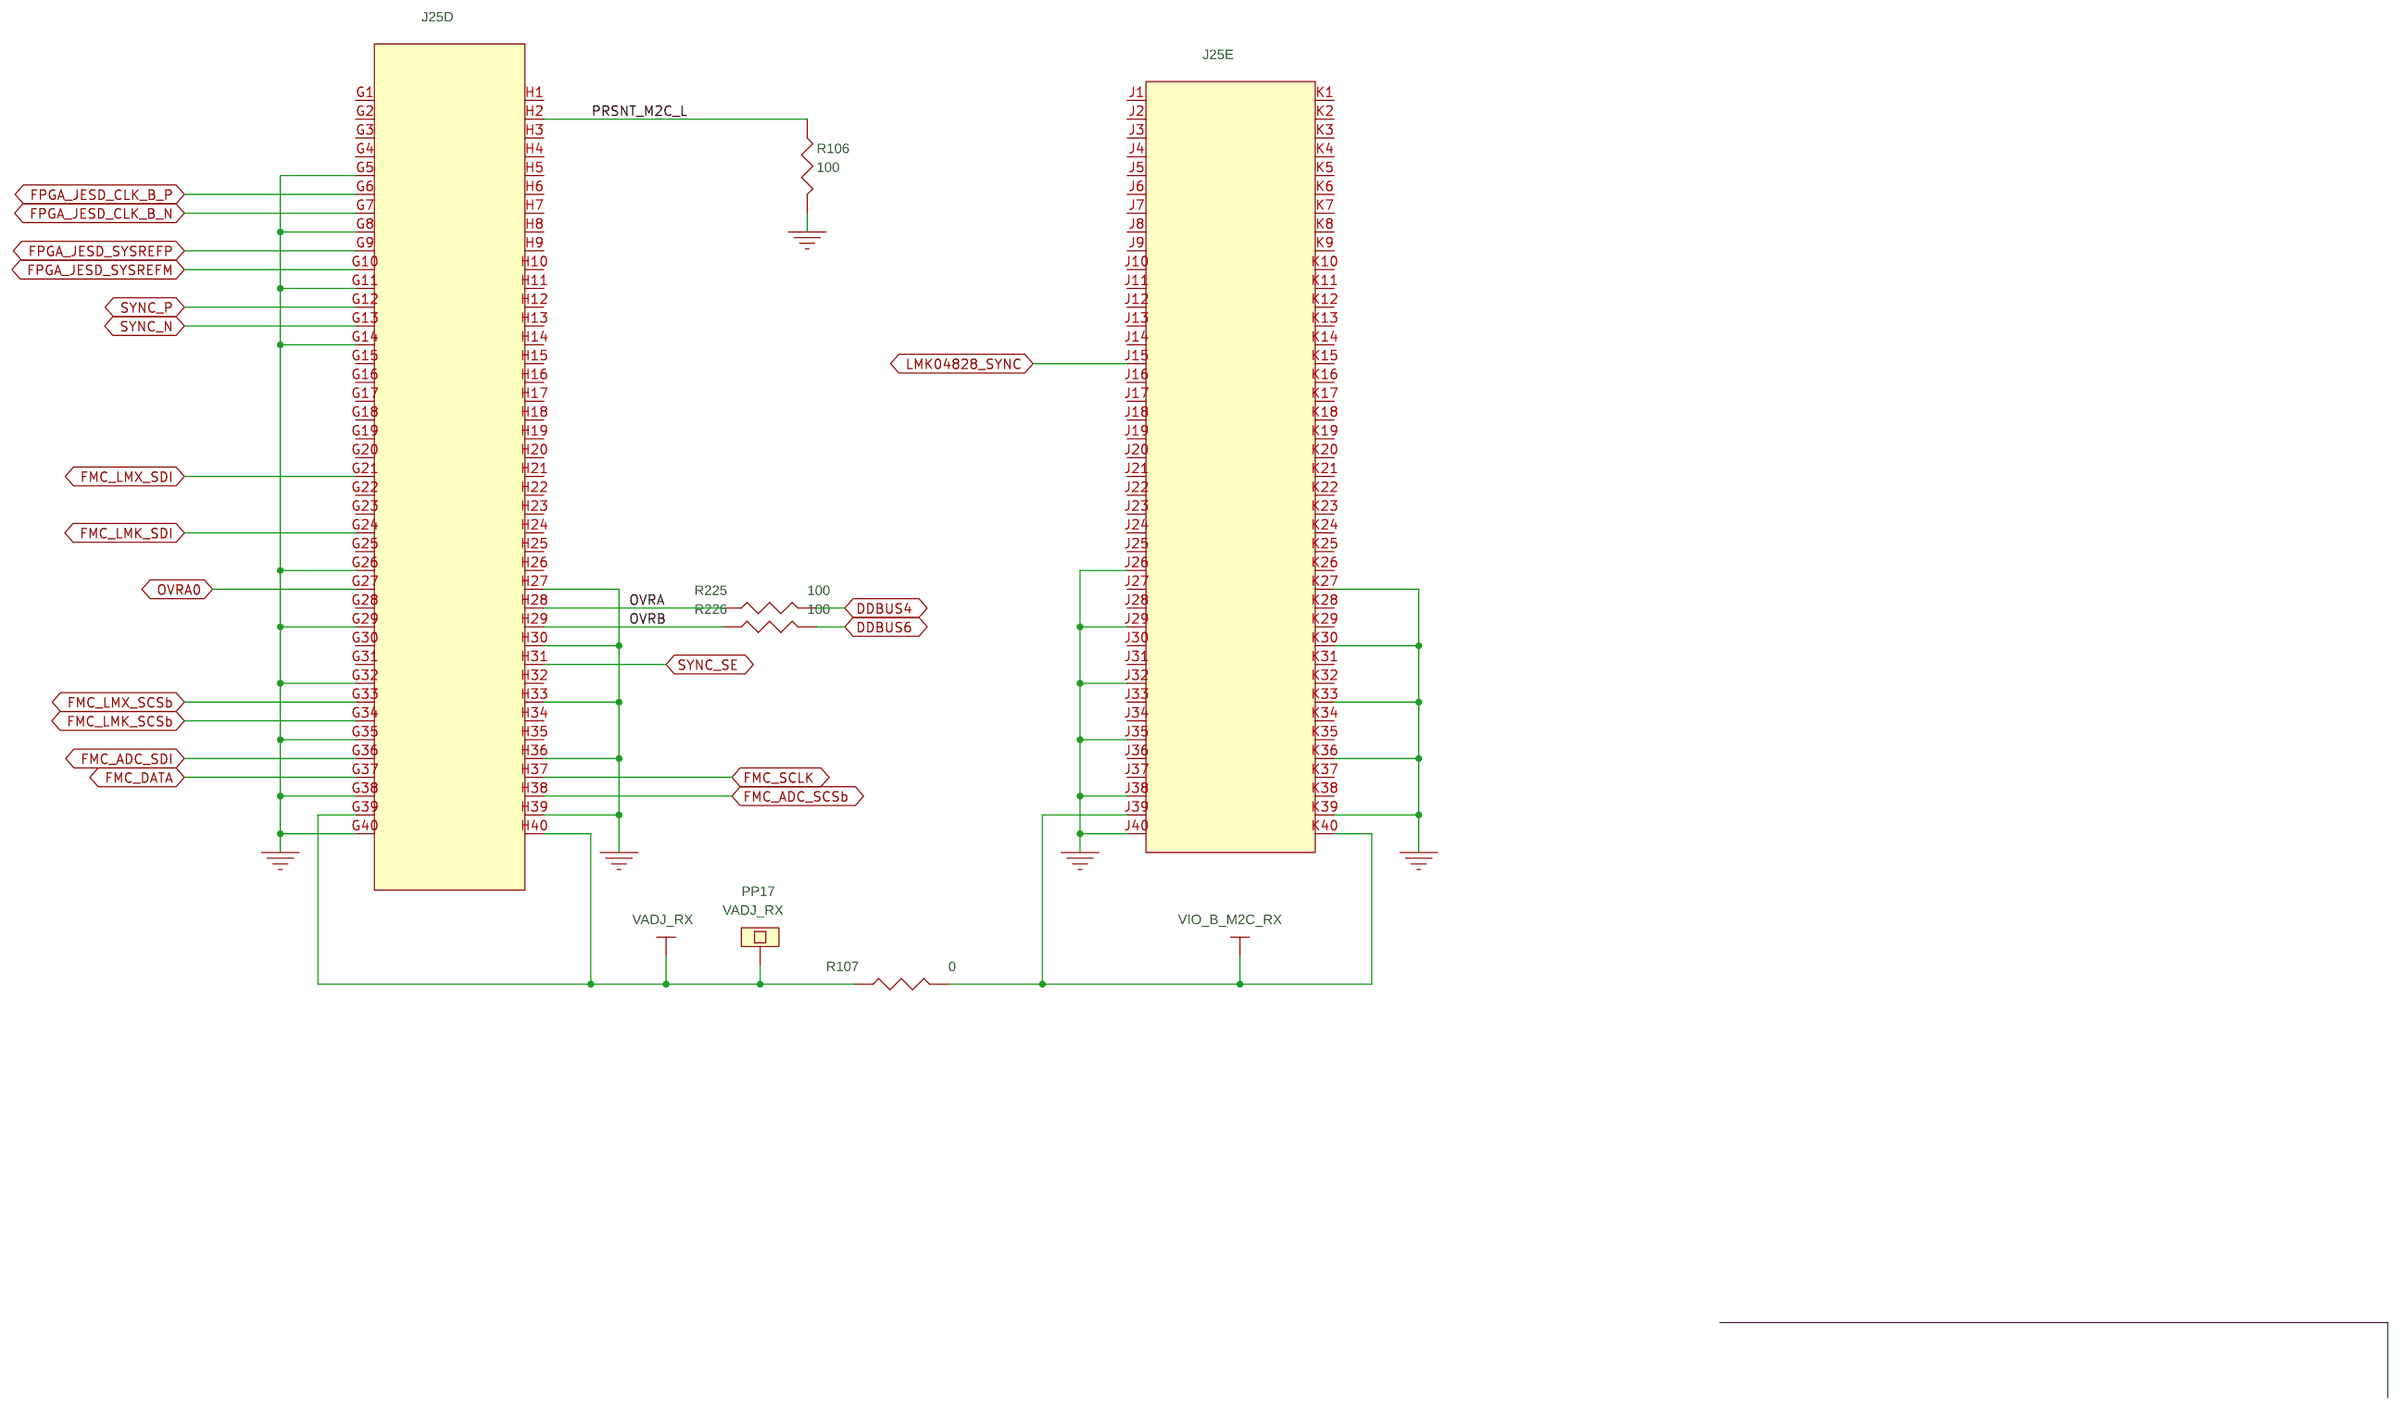
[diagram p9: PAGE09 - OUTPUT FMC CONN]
11 PAGE10 - OUTPUT FMC CONN: size B; title: ADC12DJ3200EVMCVAL (FMC)
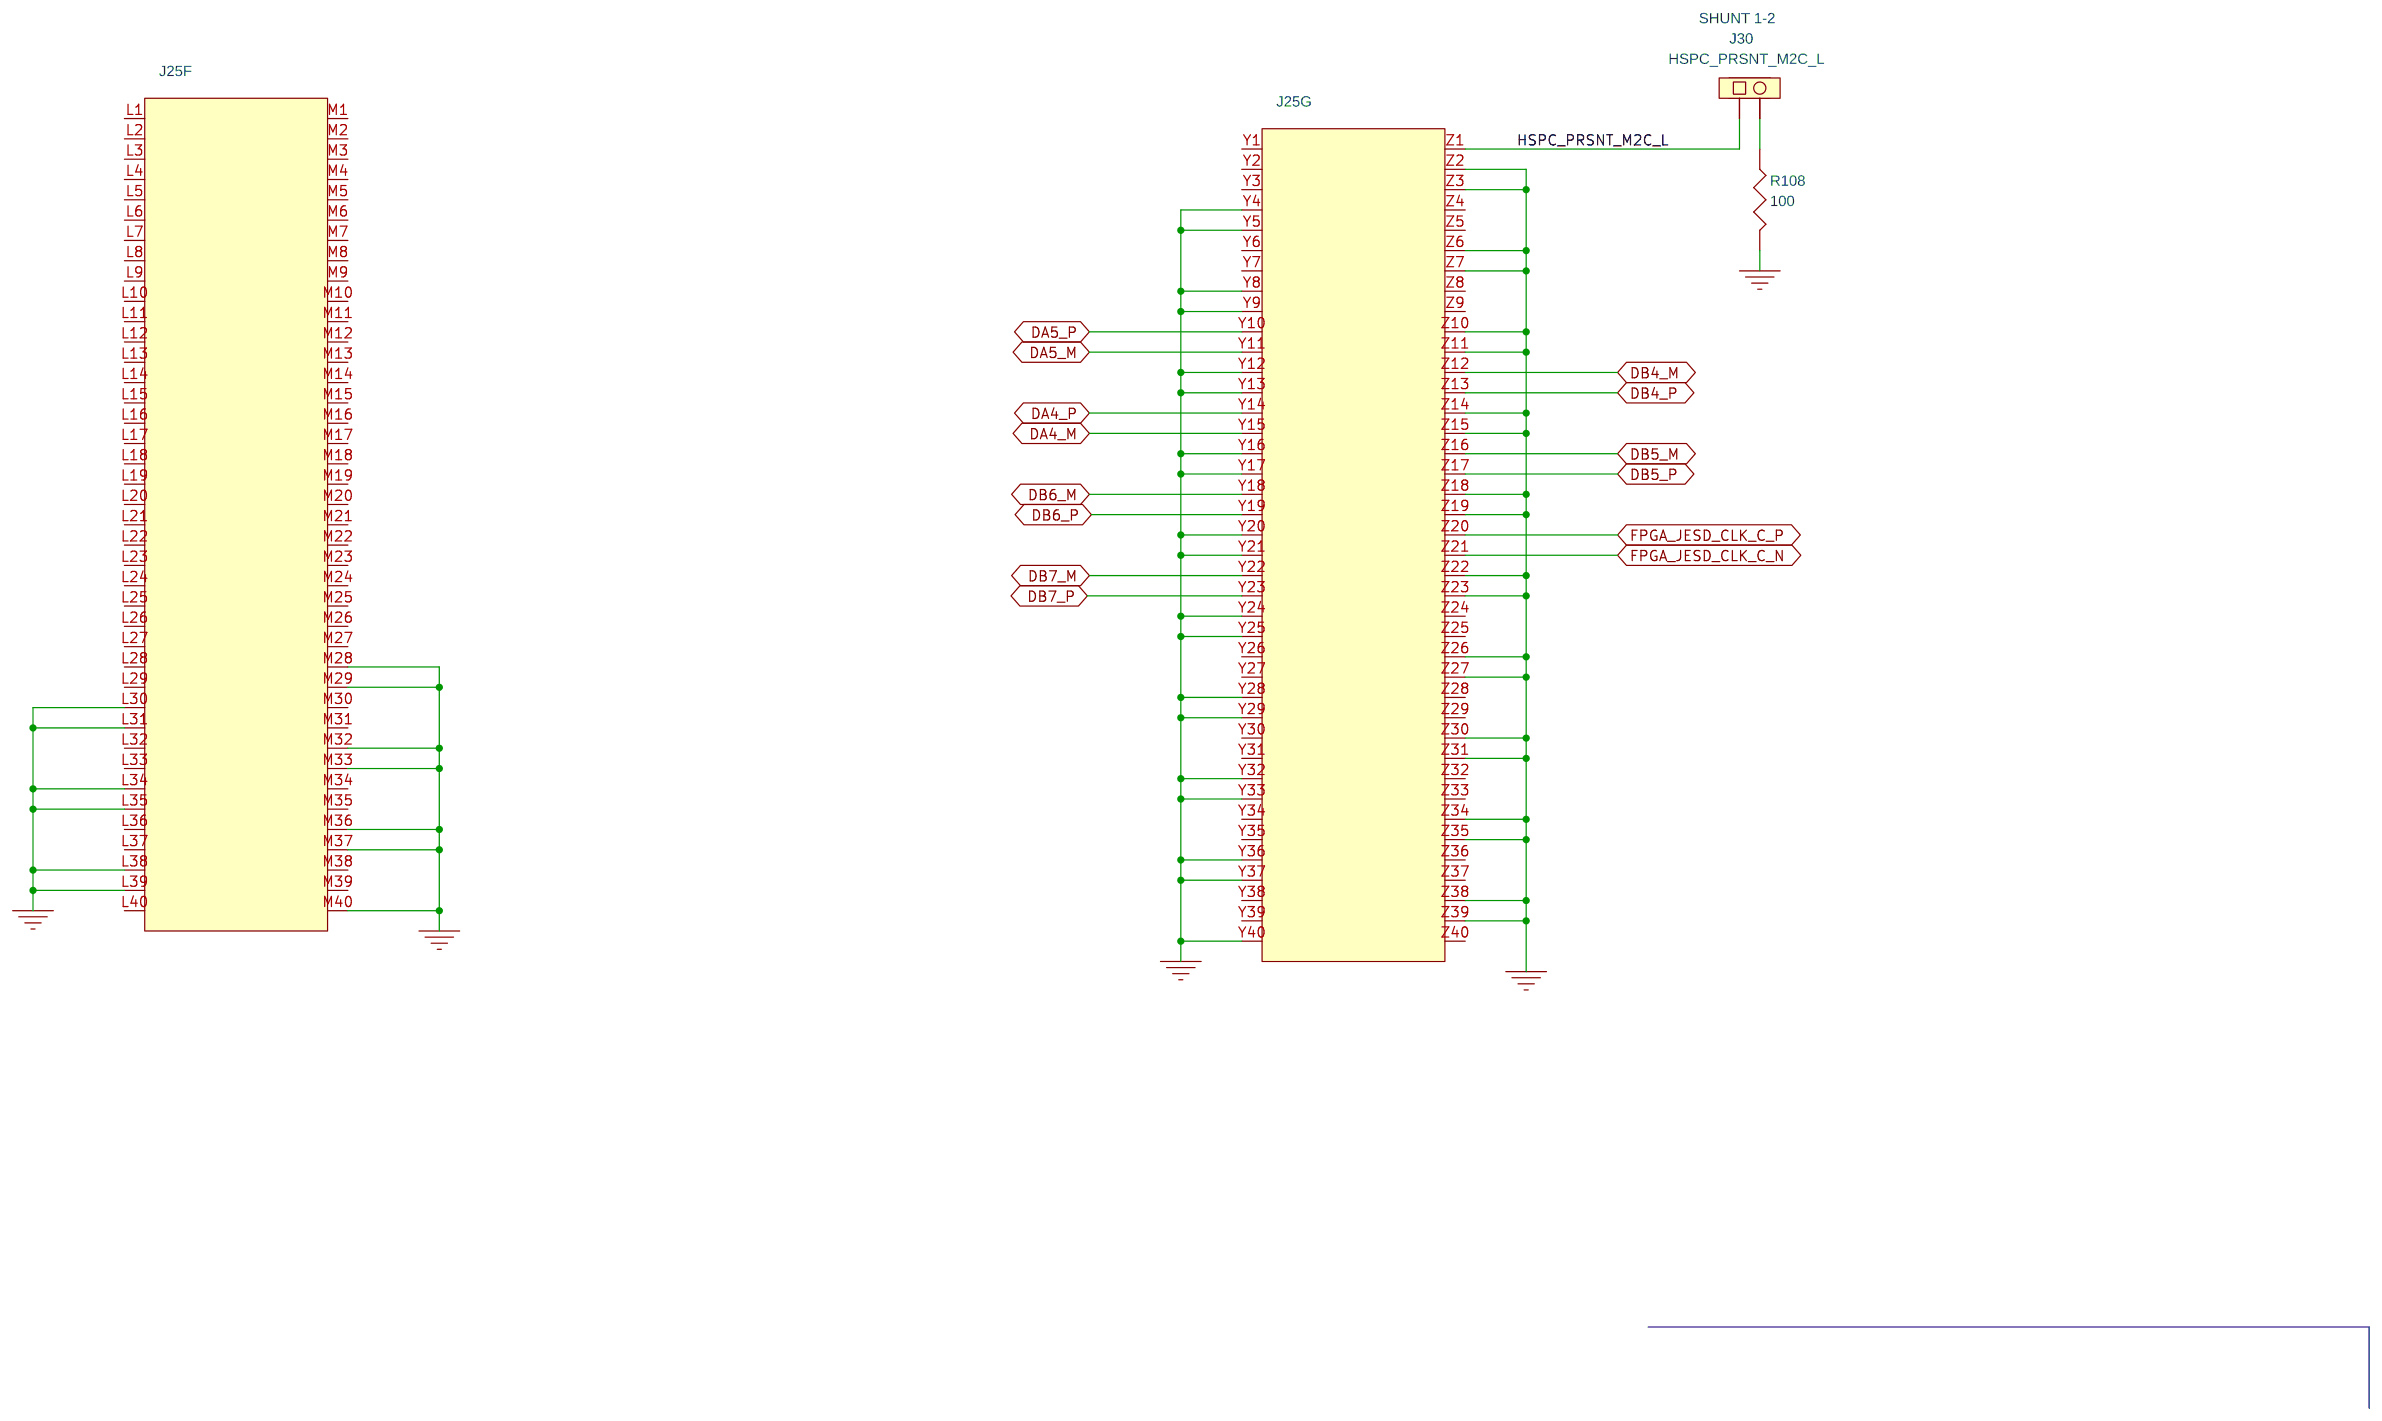
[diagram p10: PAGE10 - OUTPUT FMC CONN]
12 PAGE11 - USB: size B; title: ADC12DJ3200EVMCVAL (USB)
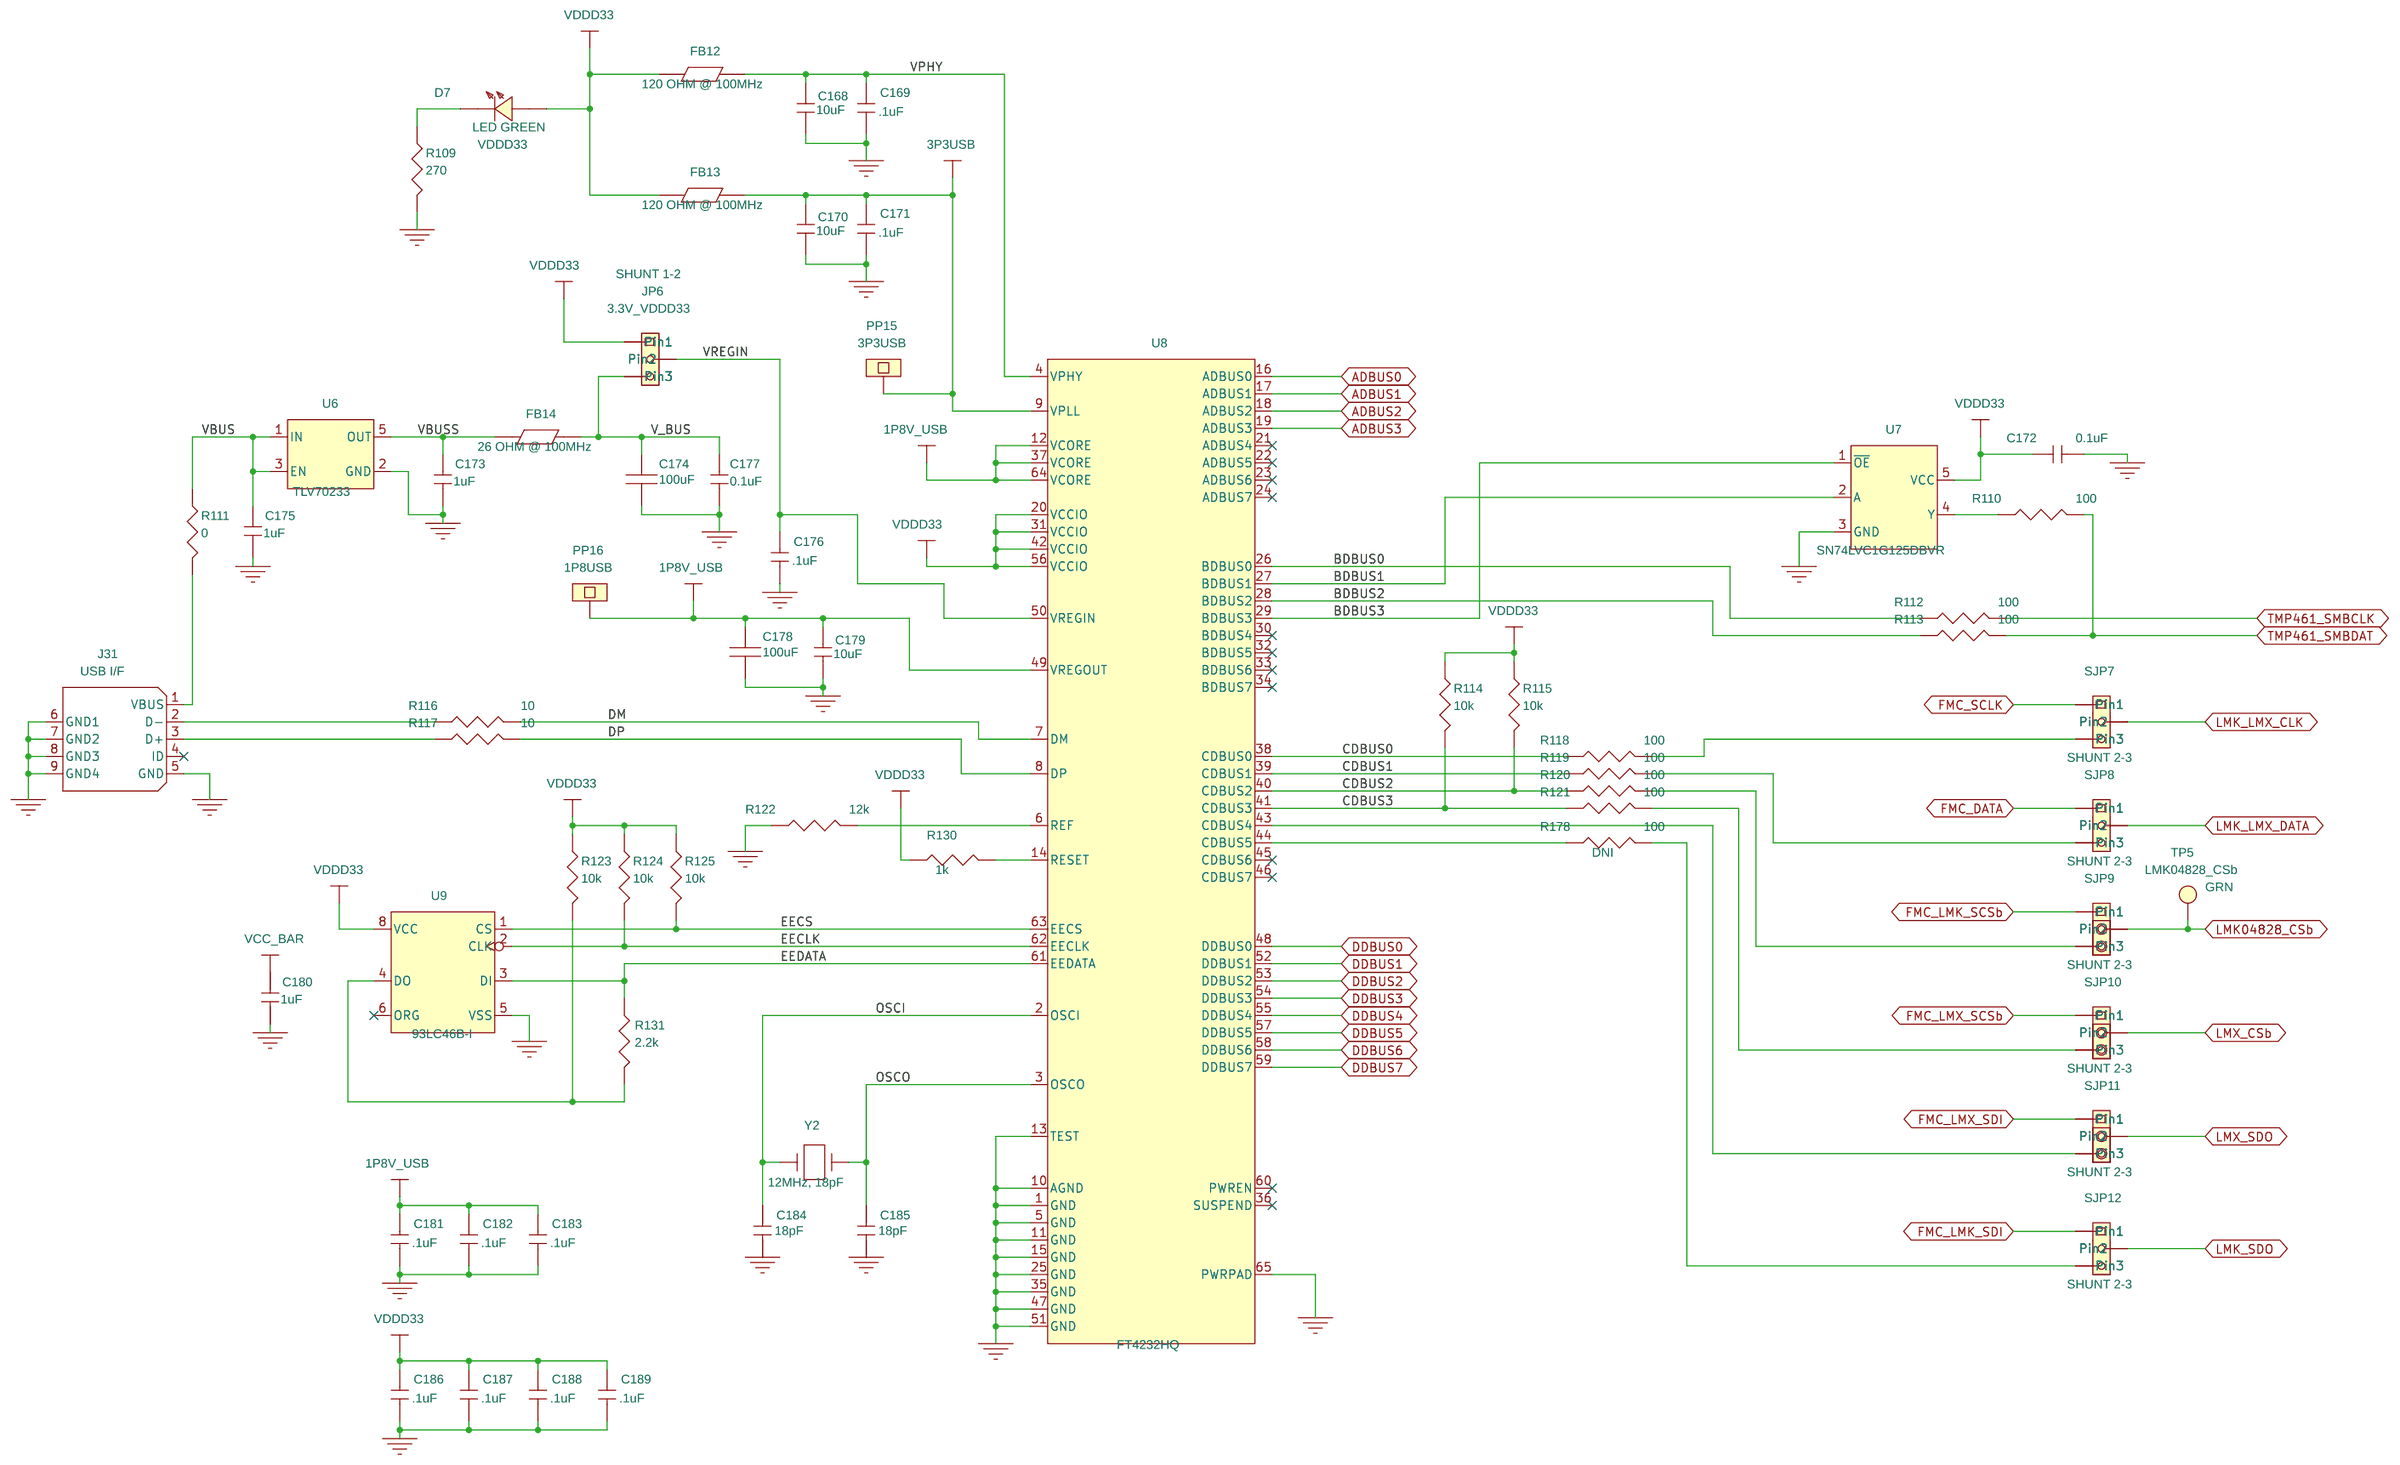
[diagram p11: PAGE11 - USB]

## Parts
sheet PAGE02 - ADC ANALOG INPUT
BALUN1  BALUN, HIGH POWER, SMT  [BALUN_320x320_MARKI_0006SMG]
BALUN2  BALUN, HIGH POWER, SMT  [BALUN_320x320_MARKI_0006SMG]
C5  .1uF  [0201]
C6  .1uF  [0201]
C7  .1uF  [0201]
C8  .1uF  [0201]
C9  .1uF  [0201]
C10  .1uF  [0201]
C11  .1uF  [0201]
C12  .1uF  [0201]
C13  .1uF  [0201]
C15  .1uF  [0201]
C16  .1uF  [0201]
C18  .1uF  [0201]
C19  .1uF  [0201]
C21  .1uF  [0201]
C22  .1uF  [0201]
C23  .1uF  [0201]
C25  .1uF  [0201]
C26  .1uF  [0201]
C27  .1uF  [0201]
C28  .1uF  [0201]
C29  .1uF  [0201]
C30  .1uF  [0201]
C31  .1uF  [0201]
C32  .1uF  [0201]
C33  .1uF  [0201]
C34  .1uF  [0201]
C35  .1uF  [0201]
C36  .1uF  [0201]
C37  .1uF  [0201]
C38  .1uF  [0201]
C39  .1uF  [0201]
C40  .1uF  [0201]
J1  SMP, PCB, SMT  [SMP_B120]
J2  SMA, THVT, SMT CENTER PIN  [SMA_THVT_SMT_250x250]
J3  SMP, PCB, SMT  [SMP_B120]
J4  SMP, PCB, SMT  [SMP_B120]
J5  SMA, THVT, SMT CENTER PIN  [SMA_THVT_SMT_250x250]
J6  SMP, PCB, SMT  [SMP_B120]
J7  HDR, THVT, 8POS, .100, GOLD  [HDR_THVT_2x4_100_M]
R1  0  [0201]
R4  0  [0201]
R6  0  [0201]
R9  0  [0201]
R11  10k  [0402]
R12  10k  [0402]
R13  1k  [0402]
R14  1k  [0402]
R15  1k  [0402]
R16  1k  [0402]
R17  10k  [0402]
R18  10k  [0402]
R151  0  [0201]
R162  0  [0201]
R179  0  [0201]
R180  0  [0201]
sheet PAGE03 - ADC SPI
C1  0.1uF  [0603]
C2  1uF  [0603]
C3  .1uF  [0402]
C4  .1uF  [0402]
C14  .1uF  [0402]
C41  100pF  [0402]
C42  .1uF  [0402]
C43  10uF  [TANT_B]
C44  100pF  [0402]
C45  .1uF  [0402]
C47  .1uF  [0402]
C48  4700pF  [0402]
C49  4700pF  [0402]
C50  4700pF  [0402]
C51  4700pF  [0402]
C52  4700pF  [0402]
C53  4700pF  [0402]
D1  LED RED  [LED_0805]
D9  1N4148W  [DIODE_SM_1N4148W]
D10  LED ORANGE  [LED_0805]
D11  LED ORANGE  [LED_0805]
D12  1N4148W  [DIODE_SM_1N4148W]
J8  HDR, THVT, 2POS, .100, GOLD  [HDR_THVT_1x2_100_M]
J9  HDR, THVT, 2POS, .100, GOLD  [HDR_THVT_1x2_100_M]
J14  SMA, JACK, 50 OHM, EDGE MNT  [SMA_SMEL_373x312]
J15  SMA, JACK, 50 OHM, EDGE MNT  [SMA_SMEL_373x312]
J17  HDR, THVT, 2POS, .100, GOLD  [HDR_THVT_1x2_100_M]
J18  SMA, JACK, 50 OHM, EDGE MNT  [SMA_SMEL_373x312]
R19  1k  [0402]
R20  1k  [0402]
R21  10k  [0402]
R23  10k  [0402]
R25  1k  [0402]
R26  2.1k  [0402]
R27  10k  [0402]
R28  10k  [0402]
R30  8.06k  [0402]
R31  1M  [0402]
R32  1.2k  [0402]
R33  1.33k  [0402]
R34  0  [0402]
R35  0  [0402]
R36  0  [0402]
R37  750  [0402]
R38  0  [0402]
R39  1.3k  [0402]
R40  0  [0402]
R41  1.3k  [0402]
R42  0  [0402]
R43  100  [0402]
R184  1M  [0402]
R185  1.2k  [0402]
T2  TC1-1-43X-4+  [TFMR_5_150x150_50]
TP1  ORN  [TP_THVT_100_RND]
TP2  ORN  [TP_THVT_100_RND]
TP9  ORN  [TP_THVT_100_RND]
TP10  ORN  [TP_THVT_100_RND]
U1  ADC12DJ3200-CVAL  [BGA_196_1mm_via_in_pad]  (sections A,B,C,D)
U2  TMP461  [QFN_10_83x83_RUN]
U15  LMC6762  [SOIC_8_197x157_50]  (sections A,B)
sheet PAGE04 - ADC PWR
C54  .1uF  [0201]
C55  .1uF  [0201]
C56  .1uF  [0201]
C57  .1uF  [0201]
C58  .1uF  [0201]
C59  .1uF  [0201]
C60  .1uF  [0201]
C61  .1uF  [0201]
C62  .1uF  [0201]
C63  .1uF  [0201]
C64  .1uF  [0201]
C65  .1uF  [0201]
C66  1uF  [0402]
C67  1uF  [0402]
C68  10uF  [TANT_B]
C69  .1uF  [0201]
C70  .1uF  [0201]
C71  .1uF  [0201]
C72  .1uF  [0201]
C73  .1uF  [0201]
C74  .1uF  [0201]
C75  .1uF  [0201]
C76  .1uF  [0201]
C77  .1uF  [0201]
C78  .1uF  [0201]
C79  .1uF  [0201]
C80  .1uF  [0201]
C81  1uF  [0402]
C82  1uF  [0402]
C83  10uF  [TANT_B]
C84  .1uF  [0201]
C85  .1uF  [0201]
C86  .1uF  [0201]
C87  .1uF  [0201]
C88  .1uF  [0201]
C89  .1uF  [0201]
C90  .1uF  [0201]
C91  .1uF  [0201]
C92  .1uF  [0201]
C93  .1uF  [0201]
C94  1uF  [0402]
C95  10uF  [TANT_B]
C96  .1uF  [0201]
PP19  PROBE POINT  [PROBE_POINT_30PAD]
PP20  PROBE POINT  [PROBE_POINT_30PAD]
PP21  PROBE POINT  [PROBE_POINT_30PAD]
sheet PAGE05 - LMX
C99  100pF  [0201]
C100  .1uF  [0201]
C101  .1uF  [0201]
C102  1uF  [0402]
C103  .1uF  [0201]
C104  .1uF  [0201]
C105  100pF  [0201]
C106  .1uF  [0201]
C107  .1uF  [0201]
C108  100pF  [0201]
C109  .1uF  [0201]
C110  100pF  [0201]
C111  1uF  [0402]
C112  10uF  [0603]
C113  .1uF  [0201]
C114  1uF  [0402]
C115  10uF  [0603]
C116  10uF  [0603]
C117  1uF  [0402]
C118  10uF  [0603]
C119  560pF  [0201]
C120  .047uF  [0201]
C121  6800pF  [0201]
C122  6800pF  [0201]
D2  LED GREEN  [LED_0805]
J20  SMP, PCB, SMT  [SMP_B120]
JP5  HDR, THVT, 2POS, .100, GOLD  [HDR_THVT_1x2_100_M]
R44  49.9  [0402]
R45  49.9  [0402]
R46  12k  [0402]
R47  100  [0402]
R48  49.9  [0402]
R49  49.9  [0402]
R50  680  [0201]
R51  680  [0201]
R52  49.9  [0201]
R53  49.9  [0201]
R54  0  [0201]
R55  12  [0201]
R56  150  [0201]
U3  LMX2582  [qfn40_RTA_RTB_RHA]
sheet PAGE06 - LMK
C20  .1uF  [0201]
C24  .1uF  [0201]
C128  .68uF  [0402]
C130  .1uF  [0201]
C131  3900pF  [0201]
C132  47pF  [0201]
C133  .1uF  [0201]
C134  .01uF  [0201]
C135  .1uF  [0201]
C136  .01uF  [0201]
C137  .1uF  [0201]
C138  .1uF  [0201]
C139  100pF  [0402]
C140  2200pF  [0402]
C141  10pF  [0402]
C142  .1uF  [0201]
C143  .1uF  [0201]
C144  .1uF  [0201]
C145  .1uF  [0201]
C146  .1uF  [0201]
C149  .1uF  [0201]
C150  .1uF  [0201]
C151  .1uF  [0201]
C152  12pF  [0201]
C153  .1uF  [0201]
C249  .1uF  [0201]
C250  .1uF  [0201]
FB1  120 OHM @ 100MHz  [IND_0603]
J22  SMA_THVT_REC  [SMA_THVT_312x312]
J23  SMA, THVT, SMT CENTER PIN  [SMA_THVT_SMT_250x250]
J24  SMA, THVT, SMT CENTER PIN  [SMA_THVT_SMT_250x250]
J38  SMA_THVT_REC  [SMA_THVT_312x312]
R22  0  [0201]
R24  0  [0201]
R57  240  [0201]
R58  240  [0201]
R59  0  [0201]
R60  0  [0201]
R61  240  [0201]
R62  240  [0201]
R63  39k  [0201]
R64  240  [0201]
R65  240  [0201]
R66  620  [0201]
R67  0  [0402]
R68  49.9  [0201]
R69  0  [0603]
R70  18  [0402]
R71  292  [0402]
R72  292  [0402]
R73  100  [0402]
R74  120  [0201]
R75  120  [0201]
R76  0  [0201]
R77  0  [0201]
R78  120  [0201]
R79  120  [0201]
R80  100  [0201]
R81  100  [0201]
R82  130  [0201]
R83  100  [0201]
R84  82  [0201]
R85  49.9  [0201]
R86  240  [0201]
R87  240  [0201]
R88  130  [0201]
R89  240  [0201]
R90  240  [0201]
R91  100  [0201]
R92  82  [0201]
R93  49.9  [0201]
R94  240  [0201]
R95  240  [0201]
R126  0  [0201]
R127  0  [0201]
R128  0  [0201]
R129  0  [0201]
R186  0  [0201]
R187  51  [0201]
R188  240  [0201]
R189  240  [0201]
SJP1  SOLDER JUMPER, 0402  [SMD_JUMPER_L_0402]
T1  TC1-1-13M-23+  [TFMR_5_150x150_50]
U4  LMK04832  [WQFN_64_360X360_0P5MM_PWRPAD]  (sections A,B)
Y1  100.00MHz  [VCXO_6_CUSTOM]
sheet PAGE07 - LMK POWER
C154  1uF  [0402]
C155  .1uF  [0402]
C156  0.01uF  [0402]
C157  1uF  [0402]
C158  1uF  [0402]
C159  1uF  [0402]
C160  1uF  [0402]
C161  .1uF  [0402]
C162  0.01uF  [0402]
C163  .1uF  [0402]
C164  10uF  [0603]
C165  1uF  [0402]
C166  1uF  [0402]
D3  LED GREEN  [LED_0805]
D4  LED GREEN  [LED_0805]
D5  LED GREEN  [LED_0805]
D6  LED GREEN  [LED_0805]
FB2  120 OHM @ 100MHz  [IND_0603]
FB3  120 OHM @ 100MHz  [IND_0603]
FB4  120 OHM @ 100MHz  [IND_0603]
FB5  120 OHM @ 100MHz  [IND_0603]
FB6  120 OHM @ 100MHz  [IND_0603]
FB7  120 OHM @ 100MHz  [IND_0603]
FB8  120 OHM @ 100MHz  [IND_0603]
FB9  120 OHM @ 100MHz  [IND_0603]
FB10  120 OHM @ 100MHz  [IND_0603]
FB11  120 OHM @ 100MHz  [IND_0603]
R96  2.32k  [0402]
R97  0  [0402]
R98  0  [0402]
R99  10k  [0402]
R100  750  [0603]
R101  750  [0603]
R102  750  [0603]
R103  750  [0603]
TP4  ORN  [TP_THVT_100_RND]
sheet PAGE08 - OUTPUT FMC CONN
C167  1uF  [0402]
J25  CON, SMVT, HS, FIELD ARRAY, FMC, MALE  [CON_SMVT_40X14_50_M_MTG]  (sections A,B,C,D,E,F,G)
J26  HDR, THVT, 2POS, .100, GOLD  [HDR_THVT_1X2_100_M]
J27  HDR, THVT, 2POS, .100, GOLD  [HDR_THVT_1X2_100_M]
J28  HDR, THVT, 4POS, .100, GOLD  [HDR_THVT_1x4_100_M]
PP18  PROBE POINT  [PROBE_POINT_30PAD]
R104  4.99k  [0402]
R105  0  [0402]
U5  24LC65  [SO_8_207x207_50]
sheet PAGE09 - OUTPUT FMC CONN
PP17  PROBE POINT  [PROBE_POINT_30PAD]
R106  100  [0603]
R107  0  [0402]
R225  100  [0402]
R226  100  [0402]
sheet PAGE10 - OUTPUT FMC CONN
J30  HDR, THVT, 2POS, .100, GOLD  [HDR_THVT_1X2_100_M]
R108  100  [0201]
Z_SH-J5  SHUNT- HEADER
sheet PAGE11 - USB
C168  10uF  [0603]
C169  .1uF  [0201]
C170  10uF  [0603]
C171  .1uF  [0201]
C172  0.1uF  [0603]
C173  1uF  [0603]
C174  100uF  [1206]
C175  1uF  [0603]
C176  .1uF  [0201]
C177  0.1uF  [0603]
C178  100uF  [1206]
C179  10uF  [0603]
C180  1uF  [0603]
C181  .1uF  [0201]
C182  .1uF  [0201]
C183  .1uF  [0201]
C184  18pF  [0402]
C185  18pF  [0402]
C186  .1uF  [0201]
C187  .1uF  [0201]
C188  .1uF  [0201]
C189  .1uF  [0201]
D7  LED GREEN  [LED_0805]
FB12  120 OHM @ 100MHz  [IND_0603]
FB13  120 OHM @ 100MHz  [IND_0603]
FB14  26 OHM @ 100MHz  [IND_0603]
J31  CON, USB, MINI, AB, SMT  [CON_SMRT_USBMNE20_F]
JP6  HDR, THVT, 3POS, .100, GOLD  [HDR_THVT_1x3_100_M]
PP15  PROBE POINT  [PROBE_POINT_30PAD]
PP16  PROBE POINT  [PROBE_POINT_30PAD]
R109  270  [0402]
R110  100  [0402]
R111  0  [0603]
R112  100  [0402]
R113  100  [0402]
R114  10k  [0402]
R115  10k  [0402]
R116  10  [0603]
R117  10  [0603]
R118  100  [0402]
R119  100  [0402]
R120  100  [0402]
R121  100  [0402]
R122  12k  [0603]
R123  10k  [0402]
R124  10k  [0402]
R125  10k  [0402]
R130  1k  [0603]
R131  2.2k  [0603]
R178  100  [0402]
SJP7  JUMPER_1X3_100  [JUMPER_SMD_3POS_0402]
SJP8  JUMPER_1X3_100  [JUMPER_SMD_3POS_0402]
SJP9  JUMPER_1X3_100  [JUMPER_SMD_3POS_0402]
SJP10  JUMPER_1X3_100  [JUMPER_SMD_3POS_0402]
SJP11  JUMPER_1X3_100  [JUMPER_SMD_3POS_0402]
SJP12  JUMPER_1X3_100  [JUMPER_SMD_3POS_0402]
TP5  GRN  [TP_THVT_100_RND]
U6  TLV70233  [SOT_5_120x69_37]
U7  SN74LVC1G125DBVR  [SOT_5_120x69_57]
U8  FT4232HQ  [QFN_64_0p50MM_RGC_FT2232HQ]
U9  93LC46B-I  [MSOP_8_118x118_0p65MM]
Y2  12MHz, 18pF  [XTAL_2_SM_126x197]
Z_SH-H2  SHUNT- HEADER
Z_SH-J11  SHUNT-JUMPER-0402
Z_SH-J12  SHUNT-JUMPER-0402
Z_SH-J13  SHUNT-JUMPER-0402
Z_SH-J14  SHUNT-JUMPER-0402
Z_SH-J15  SHUNT-JUMPER-0402
Z_SH-J16  SHUNT-JUMPER-0402
sheet PAGE15 - HARDWARE
MT1  STANDOFF, FEMALE, 4-40 X 1 3/16", AL  [MFG125_PLATED]
MT2  STANDOFF, FEMALE, 4-40 X 1 3/16", AL  [MFG125_PLATED]
PCB  BARE BOARD, ADC12DJ3200EVMCVAL
Z_SCREW1  SCREW, 4-40 X 3/4", PHIL, SS
Z_SCREW2  SCREW, 4-40 X 3/4", PHIL, SS

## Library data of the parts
BALUN1 BALUN2 = BALUN_MARKI_SMG_320x320: Mfr_Part_Number: BAL-0009SMG
C5-C13 C15 C16 C18 C19 C21-C23 C25-C40 C138 C149 = CAP_0402_0.1uF_H: Mfr_Part_Number: GRM033R61A104KE15D; TOL: 10%; Voltage: 16V
J1 = SMP_PLUG_SMT_0: Mfr_Name: MOLEX INC.; Mfr_Part_Number: 0853050232; TI_Silktext: INA+
J2 = SMA_THVT_SMA_CENTER_PIN: TI_Silktext: VINA
J3 = SMP_PLUG_SMT_0: Mfr_Name: MOLEX INC.; Mfr_Part_Number: 0853050232; TI_Silktext: INA-
J4 = SMP_PLUG_SMT_0: Mfr_Name: MOLEX INC.; Mfr_Part_Number: 0853050232; TI_Silktext: INB+
J5 = SMA_THVT_SMA_CENTER_PIN: TI_Silktext: VINB
J6 = SMP_PLUG_SMT_0: Mfr_Name: MOLEX INC.; Mfr_Part_Number: 0853050232; TI_Silktext: INB-
J7 = HEADER_2x4_100: Mfr_Part_Number: HTSW-104-07-G-D; TI_SILKTEXT: NCO
R1 R4 R6 R9 = Res_0201_Zero_H: Mfr_Part_Number: ERJ-1GE0R00C
R11 R12 R17 R18 R21 R23 R27 R28 R114 R115 R123-R125 = Res_0402_10k
R13-R16 = Res_0402_1k_H
R151 R162 R179 R180 = Res_0201_Zero_H: Mfr_Part_Number: ERJ-1GE0R00C_DNI; Note: DNI
C1 = CAP_0603_0.1uF: Mfr_Part_Number: 0603YC104JAT2A
C2 = CAP_0603_1uF: Mfr_Name: TDK; Mfr_Part_Number: C1608X5R1A105K080AC
C3 C4 C14 C45 C47 = CAP_0402_4700pF_H: Mfr_Name: MURATA; Mfr_Part_Number: GRM155R71C104KA88D
C41 C44 = CAP_0603_100pF: Mfr_Part_Number: 04025A101JAT2A
C42 = CAP_0603_0.1uF: Mfr_Name: MURATA; Mfr_Part_Number: GRM155R71C104KA88D
C43 C68 C83 C95 = CAP_TANT_B_10uF_10V: Mfr_Name: Vishay Sprague; Mfr_Part_Number: 293D106X0010B2TE3
C48 C49 C52 C53 = CAP_0402_4700pF_H: Mfr_Part_Number: CC0402KRX7R8BB472_DNI; Note: DNI
C50 C51 = CAP_0402_4700pF_H
D1 = LED_RED_0: TI_SILKTEXT: TEMP
D9 D12 = DIODE_1N4148W
D10 = LED_ORANGE_0603: Mfr_Part_Number: LTST-C170KFKT; SILK: OVRB0
D11 = LED_ORANGE_0603: Mfr_Part_Number: LTST-C170KFKT; SILK: OVRA0
J8 = HEADER_1x2_100: Mfr_Part_Number: HTSW-102-07-G-S; TI_SILKTEXT: PD
J9 = HEADER_1x2_100: Mfr_Part_Number: HTSW-102-07-G-S; TI_SILKTEXT: CALTRG
J14 = SMA_END_HIGH_FREQ_PSF-S01_0: Mfr_Name: Johnson Components; Mfr_Part_Number: 142-0701-801; TI_Silktext: TMSTP+
J15 = SMA_END_HIGH_FREQ_PSF-S01_0: Mfr_Name: Johnson Components; Mfr_Part_Number: 142-0701-801; TI_Silktext: TMSTP-
J17 = HEADER_1x2_100: Mfr_Part_Number: HTSW-102-07-G-S_DNI; Note: DNI; TI_SILKTEXT: TDIODE
J18 = SMA_END_HIGH_FREQ_PSF-S01_0: Mfr_Name: Johnson Components; Mfr_Part_Number: 142-0701-801; TI_Silktext: DEVCLK+
R19 R20 R25 = Res_0402_1k
R26 = Res_0402_2.1K
R30 = Res_0402_8.06k
R31 R184 = Res_0402_1M
R32 R185 = Res_0402_1.2k
R33 = Res_0402_1.33k
R34 R38 R97 = Res_0402_Zero_H
R35 R36 R98 = Res_0402_Zero_H: Mfr_Part_Number: ERJ-2GE0R00X_DNI; Note: DNI
R37 = Res_0603_750_H: Mfr_Part_Number: ERJ-2RKF7500X
R39 R41 = Res_0603_1.3k_H: Mfr_Part_Number: ERJ-2RKF1301X
R40 R42 = Res_0402_Zero_H: Mfr_Part_Number: ERJ-2GE0R00X
R43 R47 R225 R226 = Res_0402_100_H
T2 = TFMR_5_TC1-1-43X+
TP1 = TESTPOINT_ORANGE: TI_SILKTEXT: TCRIT1
TP2 = TESTPOINT_ORANGE: TI_SILKTEXT: TCRIT2
TP9 = TESTPOINT_ORANGE: TI_SILKTEXT: BG
TP10 = TESTPOINT_ORANGE: TI_SILKTEXT: CALSTAT
U1 = ADC12DJ1350_196PIN: Mfr_Name: Texas Instruments
U2 = TMP461
U15 = LMC6762: Mfr_Part_Number: LMC6762AIM/NOPB
C54-C65 C69-C80 C84-C93 C96 = CAP0402_0: Mfr_Name: MURATA; Mfr_Part_Number: GRM033R61A104KE15D; TOL: 10%; Voltage: 16V
C66 C67 C81 C82 C94 = CAP_NP_1: Mfr_Name: YAGEO; Mfr_Part_Number: CC0402KRX7R5BB105; TOL: 10%; VOLTAGE: 6.3V
PP19 = PROBE_POINT_0: TI_Silktext: VA11
PP20 = PROBE_POINT_0: TI_Silktext: VA19
PP21 = PROBE_POINT_0: TI_Silktext: VD11
C99 C105 C108 C110 = CAP_0603_100pF_H: Mfr_Name: MURATA; Mfr_Part_Number: GRM0335C1E101JA01D
C20 C24 C100 C101 C103 C104 C106 C107 C109 C113 C133 C135 C142 C143 C146 C249 C250 = CAPACITOR_NP_1: Mfr_Name: MURATA; Mfr_Part_Number: GRM033R61A104KE15D; TOL: 10%; Voltage: 16V
C102 C111 C114 C117 = CAP_NP_0: Mfr_Name: YAGEO; Mfr_Part_Number: CC0402KRX7R5BB105; TOL: 10%; VOLTAGE: 6.3V
C112 C115 C116 C118 = CAP_NP_1: Mfr_Name: TDK; Mfr_Part_Number: C1608X5R1A106K080AC; TOL: 10%; VOLTAGE: 10V
C119 = CAP_NP_0: Mfr_Name: MURATA; Mfr_Part_Number: GRM033R71E561KA01D; TOL: 10%; VOLTAGE: 25V
C120 = CAP_NP_0: Mfr_Name: MURATA; Mfr_Part_Number: GRM033R61C473KE84D; TOL: 10%; VOLTAGE: 16V
C121 = CAP_NP_0: Mfr_Name: MURATA; Mfr_Part_Number: GRM033R71A682KA01D_DNI; Note: DNI; TOL: 10%; VOLTAGE: 10V
C122 = CAP_NP_0: Mfr_Name: MURATA; Mfr_Part_Number: GRM033R71A682KA01D; TOL: 10%; VOLTAGE: 10V
D2 = LED: Mfr_Name: LITE ON; Mfr_Part_Number: LTST-C170KGKT; TI_Silktext: MUXout
J20 = SMP_PLUG_SMT_0: Mfr_Name: MOLEX INC.; Mfr_Part_Number: 0853050232; TI_Silktext: RFOUTBP
JP5 = HDR_2x1_100: Mfr_Part_Number: HTSW-102-07-G-S; Note: OPEN
R44 R45 R48 R49 = Res_0402_49.9: Mfr_Part_Number: ERJ-2RKF49R9X
R46 = Res_0402_18: Mfr_Part_Number: ERJ-2RKF1202X
R50 = Res_0402_49.9: Mfr_Part_Number: ERJ-1GEF6800C_DNI; Note: DNI
R51 = Res_0402_49.9: Mfr_Part_Number: ERJ-1GEF6800C
R52 R53 R68 = Res_0402_49.9: Mfr_Part_Number: ERJ-1GEF49R9C_DNI; Note: DNI
R22 R24 R54 R59 R60 R76 R77 R126-R129 R186 = Res_0402_Zero_H_DNI: Mfr_Part_Number: ERJ-1GE0R00C
R55 = Res_0402_18: Mfr_Part_Number: ERJ-1GEF12R0C
R56 = R_1: Mfr_Name: PANASONIC; Mfr_Part_Number: ERJ-1GEJ151C
U3 = LMX2582_LM2592: Mfr_Name: Texas Instruments; Mfr_Part_Number: LMX2582RHAT
C128 = CAP_NP_0: Mfr_Name: TDK; Mfr_Part_Number: C1005X7S0J684K050BC; TOL: 10%; VOLTAGE: 6.3V
C130 C150 = CAP_NP_0: Mfr_Name: MURATA; Mfr_Part_Number: GRM033R61A104KE15D; TOL: 10%; VOLTAGE: 16V
C131 = CAP_NP_0: Mfr_Name: AVX; Mfr_Part_Number: 0201ZD392KAT2A; TOL: 10%; VOLTAGE: 10V
C132 = CAP_NP_0: Mfr_Name: MURATA; Mfr_Part_Number: GRM0335C1E470JA01D; TOL: 5%; VOLTAGE: 25V
C134 C136 = CAP_0402_0.01uF_H: Mfr_Part_Number: GRM033R71A103KA01D; TOL: 10%; VOLTAGE: 10V
C137 = CAP_0402_0.1uF: Mfr_Name: MURATA; Mfr_Part_Number: GRM033R61A104KE15D_DNI; Note: DNI; TOL: 10%; VOLTAGE: 16V
C139 = CAP_0603_100pF_H: Mfr_Name: TDK; Mfr_Part_Number: C1005C0G1H101J050BA
C140 = CAP_0402_2200pF_H: Mfr_Name: MURATA; Mfr_Part_Number: GRM155R71E222KA01D
C141 = CAP_0402_10pF_H: Mfr_Part_Number: GRM1555C1H100JA01D
C144 = CAP_0402_0.1uF_H: Mfr_Part_Number: GRM033R61A104KE15D_DNI; Note: DNI; TOL: 10%
C145 = CAP_NP_0: Mfr_Name: MURATA; Mfr_Part_Number: GRM033R61A104KE15D_DNI; Note: DNI; TOL: 10%; VOLTAGE: 16V
C151 C153 = CAPACITOR_NP_1: Mfr_Name: MURATA; Mfr_Part_Number: GRM033R61A104KE15D_DNI; Note: DNI; TOL: 10%; Voltage: 16V
C152 = CAPACITOR_NP_1: Mfr_Name: MURATA; Mfr_Part_Number: GRM0335C1H120GA01D; TOL: 2%; Voltage: 50V
FB1 = FERRITE_BEAD_0402_H: Isat: 500mA; Mfr_Name: MURATA; Mfr_Part_Number: BLM18SG121TN1D
J22 = SMA-THVT_142-0701-201_REC_0: TI_Silktext: LMK_CLKIN
J23 = SMA_THVT_SMA_CENTER_PIN: TI_Silktext: DCLKOUT10P
J24 = SMA_THVT_SMA_CENTER_PIN: TI_Silktext: DCLKOUT10N
J38 = SMA-THVT_142-0701-201_REC_0: TI_Silktext: CLKIN0
R57 R58 R61 R62 R64 R65 R89 R90 = Res_0402_249: Mfr_Part_Number: ERJ-1GEF2400C_DNI; Note: DNI
R63 = R_1: Mfr_Name: PANASONIC; Mfr_Part_Number: ERJ-1GEF3902C
R66 = R_1: Mfr_Name: PANASONIC; Mfr_Part_Number: ERJ-1GEF6200C
R67 = R: Mfr_Name: PANASONIC; Mfr_Part_Number: ERJ-2GE0R00X
R69 = Res_0603_Zero_DNI: Mfr_Part_Number: ERJ-3GEY0R00V_DNI; Note: DNI
R70 = Res_0402_18: Mfr_Part_Number: ERJ-2RKF18R0X_DNI; Note: DNI
R71 = Res_0402_270: Mfr_Part_Number: ERJ-2RKF2940X
R72 = Res_0402_270: Mfr_Part_Number: ERJ-2RKF2940X_DNI; Note: DNI
R73 = Res_0603_100: Mfr_Part_Number: ERJ-2RKF1000X
R74 R75 R78 R79 = Res_0402_249: Mfr_Part_Number: ERJ-1GEF1200C
R80 R81 = Res_0603_100: Mfr_Part_Number: ERJ-1GEF1000C_DNI; Note: DNI
R82 = RESISTOR_0: Mfr_Name: PANASONIC; Mfr_Part_Number: ERJ-1GEF1300C_DNI; Note: DNI
R83 = Res_0402_100_H: Mfr_Part_Number: ERJ-1GEF1000C_DNI; Note: DNI
R84 R92 = RESISTOR_0: Mfr_Name: PANASONIC; Mfr_Part_Number: ERJ-1GEF82R0C_DNI; Note: DNI; TOL: 1%
R85 = RESISTOR_0: Mfr_Name: PANASONIC; Mfr_Part_Number: ERJ-1GEF49R9C_DNI; Note: DNI; TOL: 1%
R86 R87 R94 R95 R188 R189 = Res_0402_249: Mfr_Part_Number: ERJ-1GEF2400C
R88 = RESISTOR_0: Mfr_Name: PANASONIC; Mfr_Part_Number: ERJ-1GEF1300C_DNI; Note: DNI; TOL: 1%
R91 = Res_0402_100_H: Mfr_Part_Number: ERJ-1GEF1000C
R93 = RESISTOR_0: Mfr_Name: PANASONIC; Mfr_Part_Number: ERJ-1GEF49R9C; TOL: 1%
R187 = Res_0201_51_1%
SJP1 = SMD_JUMPER_1x3: Mfr_Name: DNI; Mfr_Part_Number: DNI; Note: DNI; TI_SILK: SHUNT 1-2; TI_Silktext: EN
T1 = TFMR_5_TC1-1-13M+
U4 = LMK04828: Mfr_Name: Texas Instruments; Mfr_Part_Number: LMK04832NKDT
Y1 = OSC_SM_6_TCO-2100-SERIES_2: Mfr_Name: Crystek; Mfr_Part_Number: CVHD-950-100.000
C154 C157-C160 C165 C166 = CAPACITOR_NP_1: Mfr_Name: YAGEO; Mfr_Part_Number: CC0402KRX7R5BB105; TOL: 10%; Voltage: 6.3V
C155 C161 C163 = CAPACITOR_NP_1: Mfr_Name: MURATA; Mfr_Part_Number: GRM155R71C104KA88D; TOL: 10%; Voltage: 16V
C156 C162 = CAPACITOR_NP_1: Mfr_Name: MURATA; Mfr_Part_Number: GRM155R71H103KA88D; TOL: 10%; Voltage: 50V
C164 = CAP_0603_10uF: CLASS: DISCRETE; Mfr_Name: MURATA; Mfr_Part_Number: GRM188R60J106ME47D
D3 = LED: Mfr_Name: LITE ON; Mfr_Part_Number: LTST-C170KGKT; TI_Silktext: STAT 0
D4 = LED: Mfr_Name: LITE ON; Mfr_Part_Number: LTST-C170KGKT; TI_Silktext: STAT 1
D5 = LED: Mfr_Name: LITE ON; Mfr_Part_Number: LTST-C170KGKT; TI_Silktext: LMK LOCKED
D6 = LED: Mfr_Name: LITE ON; Mfr_Part_Number: LTST-C170KGKT; TI_Silktext: PLL2 LOCKED
FB2-FB11 = FERRITE_BEAD_0402_H: Isat: 500mA; Mfr_Name: MURATA; Mfr_Part_Number: BLM18AG121SN1D
R96 = Res_0402_2.32K_H
R99 = Res_0402_1.3K: Mfr_Part_Number: ERJ-2RKF1002X
R100-R103 = RESISTOR_0: CLASS: DISCRETE; Mfr_Name: DALE; Mfr_Part_Number: CRCW0603750RFKEA
TP4 = TESTPOINT_BLUE: Mfr_Part_Number: 5003; TI_SILKTEXT: LMK_SYNC
C167 = CAP_NP_1: Mfr_Name: YAGEO; Mfr_Part_Number: CC0402KRX7R5BB105
J25 = CON_SMVT_40X14_50_M
J26 = JUMPER_1X2_100: SILK: PG_RX1
J27 = JUMPER_1X2_100: SILK: JTAG Loopback
J28 = HEADER_1x4_100: TI_SILKTEXT: 3.3VAUX
PP18 = PROBE_POINT_0: TI_Silktext: 3.3VRX
R104 = Res_0402_4.99K
R105 R107 = Res_0402_Zero: Mfr_Part_Number: ERJ-2GE0R00X
U5 = 24LC65: Mfr_Name: MICROCHIP TECHNOLOGY_DNI; Mfr_Part_Number: 24C65T-I/SM_DNI; Note: DNI
PP17 = PROBE_POINT_0: TI_Silktext: VADJ_RX
R106 = Res_0201_100: Mfr_Part_Number: ERJ-3EKF1000V
J30 = JUMPER_1X2_100: Note: SHUNT 1-2; SILK: HSPC_PRSNT_M2C_L
R108 = Res_0201_100
Z_SH-J5 = SHUNT-HEADER_-_2POS
C168 C170 C179 = CAP_0603_10uF: CLASS: DISCRETE
C169 C171 C176 C181-C183 C186-C189 = CAP_0201_0.1uF: Mfr_Name: MURATA; Mfr_Part_Number: GRM033R61A104KE15D
C172 C177 = CAP_0603_0.1uF
C173 C175 C180 = CAP_0603_1uF
C174 C178 = CAP_1206_100uF_6.3V
C184 C185 = CAP_0402_18pF
D7 = LED_GREEN_0: TI_SILKTEXT: VDDD33
FB12 FB13 = FERRITE_BEAD_0603_120_H
FB14 = FERRITE_BEAD_0603_26_H
J31 = USB_MINI_AB_MNE20-5G5P10: Mfr_Name: WURTH ELEKTRONIK; Mfr_Part_Number: 651305142821; TI_SILKTEXT: USB I/F
JP6 = JUMPER_1X3_100: Mfr_Part_Number: HTSW-103-07-G-S; Note: SHUNT 1-2; TI_Silktext: 3.3V_VDDD33
PP15 = PROBE_POINT_0: TI_Silktext: 3P3USB
PP16 = PROBE_POINT_0: TI_Silktext: 1P8USB
R109 = Res_0402_270
R110 R112 R113 R118-R121 = Res_0603_100_H: Mfr_Part_Number: ERJ-2RKF1000X
R111 = Res_0603_Zero
R116 R117 = Res_0603_10
R122 = Res_0603_12k
R130 = Res_0603_1k_H
R131 = Res_0603_2.2k
R178 = Res_0603_100_H: Mfr_Part_Number: ERJ-2RKF1000X_DNI; Note: DNI
SJP7-SJP12 = JUMPER_SMD_3POS_0402: TI_Silktext: SHUNT 2-3
TP5 = TESTPOINT_GRN: TI_SILKTEXT: LMK04828_CSb
U6 = TLV702: Mfr_Part_Number: TLV70233DBVT
U7 = SN74LVC1G125DBVR: Mfr_Name: Texas Instruments
U8 = FT4232HQ
U9 = EEPROM_93LC46B: Mfr_Part_Number: 93LC46B-I/MS
Y2 = CRYSTAL_ABM3_0
Z_SH-H2 = SHUNT-HEADER_-_3POS: Mfr_Part_Number: 1-382811-6
Z_SH-J11-Z_SH-J16 = SHUNT-JUMPER-0402
MT1 MT2 = MOUNTING_HOLE: Mfr_Name: RAF; Mfr_Part_Number: 1648-440-AL
PCB = BARE_BOARD: Mfr_Name: TTM; Mfr_Part_Number: ADC12DJ3200QML REV E1
Z_SCREW1 Z_SCREW2 = STANDOFF-SCREW: Mfr_Part_Number: PMSSS 440 0075 PH; Note: SCREW FOR STANDOFF

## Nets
+3.3V_LMX: C100.1 C101.1 C102.2 C103.1 C106.1 C107.2 C113.1 C114.2 R46.2 U3.7(VccDIG) U3.11(VccCP) U3.15(VccDIV) U3.21(VccBUF) U3.26(VccDBLR) U3.37(VccVCO) ; also on sheet 15
+3.3V_LMXRF: C99.1 C105.1 R44.2 R45.2 R48.2 R49.2 ; also on sheet 15
+3.3VCLK: FB1.2 FB2.1 FB3.1 FB4.1 FB5.1 FB6.1 FB10.1 FB11.1 R82.1 R88.1 R96.2 SJP1.3(Pin3) ; also on sheet 15
GND: C1.2 C2.2 C3.1 C4.1 C14.1 C24.1 C41.2 C42.2 C43.2 C54.2 C55.2 C56.2 C57.2 C58.2 C59.2 C60.2 C61.2 C62.2 C63.2 C64.2 C65.2 C66.2 C67.2 C68.2 C69.2 C70.2 C71.2 C72.2 C73.2 C74.2 C75.2 C76.2 C77.2 C78.2 C79.2 C80.2 C81.2 C82.2 C83.2 C84.2 C85.2 C86.2 C87.2 C88.2 C89.2 C90.2 C91.2 C92.2 C93.2 C94.2 C95.2 C96.2 C99.2 C100.2 C101.2 C102.1 C103.2 C104.1 C105.2 C106.2 C107.1 C109.2 C111.1 C112.1 C113.2 C114.1 C115.1 C116.1 C117.1 C118.1 C119.2 C121.2 C122.2 C130.2 C132.2 C137.1 C138.1 C139.1 C140.1 C141.1 C146.1 C152.1 C154.1 C155.1 C156.1 C157.2 C158.2 C159.2 C160.1 C161.1 C162.1 C163.2 C164.2 C165.2 C166.2 C167.1 C168.2 C169.2 C170.2 C171.2 C172.2 C173.2 C174.2 C175.2 C176.2 C177.2 C178.2 C179.2 C180.2 C181.2 C182.2 C183.2 C184.2 C185.2 C186.2 C187.2 C188.2 C189.2 D2.2(CATHODE) D3.2(CATHODE) D4.2(CATHODE) D5.2(CATHODE) D6.2(CATHODE) J1.2(SHIELD1) J2.2(SHIELD1) J2.3(SHIELD2) J2.4(SHIELD3) J2.5(SHIELD4) J3.2(SHIELD1) J4.2(SHIELD1) J5.2(SHIELD1) J5.3(SHIELD2) J5.4(SHIELD3) J5.5(SHIELD4) J6.2(SHIELD1) J14.2(GND) J14.3(GND) J14.4(GND) J14.5(GND) J15.2(GND) J15.3(GND) J15.4(GND) J15.5(GND) J18.2(GND) J18.3(GND) J18.4(GND) J18.5(GND) J20.2(SHIELD1) J22.2(GND) J22.3(GND) J22.4(GND) J22.5(GND) J23.2(SHIELD1) J23.3(SHIELD2) J23.4(SHIELD3) J23.5(SHIELD4) J24.2(SHIELD1) J24.3(SHIELD2) J24.4(SHIELD3) J24.5(SHIELD4) J25.A1 J25.A4 J25.A5 J25.A8 J25.A9 J25.A12 J25.A13 J25.A16 J25.A17 J25.A20 J25.A21 J25.A24 J25.A25 J25.A28 J25.A29 J25.A32 J25.A33 J25.A36 J25.A37 J25.A40 J25.B3 J25.B6 J25.B7 J25.B10 J25.B11 J25.B14 J25.B15 J25.B18 J25.B22 J25.B23 J25.B26 J25.B27 J25.B30 J25.B31 J25.B34 J25.B35 J25.B38 J25.B39 J25.C1 J25.C5 J25.C8 J25.C9 J25.C21 J25.C24 J25.C25 J25.C28 J25.C29 J25.C32 J25.C33 J25.C36 J25.C38 J25.C40 J25.D3 J25.D6 J25.D7 J25.D25 J25.D28 J25.D37 J25.D39 J25.E26 J25.E29 J25.E32 J25.E35 J25.E38 J25.E40 J25.F9 J25.F27 J25.F30 J25.F33 J25.F36 J25.F39 J25.G5 J25.G8 J25.G11 J25.G14 J25.G26 J25.G29 J25.G32 J25.G35 J25.G38 J25.G40 J25.H27 J25.H30 J25.H33 J25.H36 J25.H39 J25.J26 J25.J29 J25.J32 J25.J35 J25.J38 J25.J40 J25.K27 J25.K30 J25.K33 J25.K36 J25.K39 J25.L30 J25.L31 J25.L34 J25.L35 J25.L38 J25.L39 J25.M28 J25.M29 J25.M32 J25.M33 J25.M36 J25.M37 J25.M40 J25.Y4 J25.Y5 J25.Y8 J25.Y9 J25.Y12 J25.Y13 J25.Y16 J25.Y17 J25.Y20 J25.Y21 J25.Y24 J25.Y25 J25.Y28 J25.Y29 J25.Y32 J25.Y33 J25.Y36 J25.Y37 J25.Y40 J25.Z2 J25.Z3 J25.Z6 J25.Z7 J25.Z10 J25.Z11 J25.Z14 J25.Z15 J25.Z18 J25.Z19 J25.Z22 J25.Z23 J25.Z26 J25.Z27 J25.Z30 J25.Z31 J25.Z34 J25.Z35 J25.Z38 J25.Z39 J28.3 J31.5(GND) J31.6(GND1) J31.7(GND2) J31.8(GND3) J31.9(GND4) J38.2(GND) J38.3(GND) J38.4(GND) J38.5(GND) JP5.1 MT1.1 MT2.1 R11.2 R12.2 R17.2 R18.2 R21.2 R23.2 R26.2 R31.2 R32.2 R33.2 R51.1 R52.1 R53.1 R56.2 R57.2 R58.2 R61.2 R62.2 R63.2 R64.2 R65.2 R66.2 R68.2 R71.2 R72.2 R74.2 R75.2 R78.2 R79.2 R80.2 R81.2 R84.2 R85.2 R86.2 R87.2 R89.2 R90.2 R92.2 R93.2 R94.2 R95.2 R99.2 R106.2 R108.2 R109.2 R122.1 R184.2 R185.2 R187.2 R188.2 R189.2 SJP1.1(Pin1) T1.2(secondary_ct) T1.4(primary) T2.4(primary) U1.A1(AGND) U1.A3(AGND) U1.A6(AGND) U1.A14(DGND) U1.B1(AGND) U1.B3(AGND) U1.B4(AGND) U1.B5(AGND) U1.B6(AGND) U1.B14(DGND) U1.C6(AGND) U1.C7(AGND) U1.C8(DGND) U1.C9(DGND) U1.D4(AGND) U1.D5(AGND) U1.D6(AGND) U1.D7(AGND) U1.D8(DGND) U1.D9(DGND) U1.D10(DGND) U1.D11(DGND) U1.E4(AGND) U1.E5(AGND) U1.E6(AGND) U1.E7(AGND) U1.E8(DGND) U1.E9(DGND) U1.E10(DGND) U1.E11(DGND) U1.F1(AGND) U1.F4(AGND) U1.F5(AGND) U1.F6(AGND) U1.F7(AGND) U1.F8(DGND) U1.F9(DGND) U1.F10(DGND) U1.F11(DGND) U1.G2(AGND) U1.G4(AGND) U1.G5(AGND) U1.G6(AGND) U1.G7(AGND) U1.G8(DGND) U1.G9(DGND) U1.G10(DGND) U1.G11(DGND) U1.H2(AGND) U1.H4(AGND) U1.H5(AGND) U1.H6(AGND) U1.H7(AGND) U1.H8(DGND) U1.H9(DGND) U1.H10(DGND) U1.H11(DGND) U1.J1(AGND) U1.J4(AGND) U1.J5(AGND) U1.J6(AGND) U1.J7(AGND) U1.J8(DGND) U1.J9(DGND) U1.J10(DGND) U1.J11(DGND) U1.K4(AGND) U1.K5(AGND) U1.K6(AGND) U1.K7(AGND) U1.K8(DGND) U1.K9(DGND) U1.K10(DGND) U1.K11(DGND) U1.L4(AGND) U1.L5(AGND) U1.L6(AGND) U1.L7(AGND) U1.L8(DGND) U1.L9(DGND) U1.L10(DGND) U1.L11(DGND) U1.M6(AGND) U1.M7(AGND) U1.M8(DGND) U1.M9(DGND) U1.N1(AGND) U1.N3(AGND) U1.N4(AGND) U1.N5(AGND) U1.N6(AGND) U1.N9(DGND) U1.N14(DGND) U1.P1(AGND) U1.P3(AGND) U1.P6(AGND) U1.P14(DGND) U2.5(A0) U2.6(GND) U3.2(GND) U3.4(GND) U3.6(GND) U3.13(GND) U3.14(GND) U3.25(GND) U3.31(GND) U3.34(GND) U3.39(GND) U3.40(NC4) U3.41(PWRPAD) U4.65(DAP) U5.3(A2) U5.4(VSS) U6.2(GND) U7.3(GND) U8.1(GND) U8.5(GND) U8.10(AGND) U8.11(GND) U8.13(TEST) U8.15(GND) U8.25(GND) U8.35(GND) U8.47(GND) U8.51(GND) U8.65(PWRPAD) U9.5(VSS) U15.4(V-) Y1.3(GND) ; also on sheet 13 14 15
VBUS: C175.1 R111.1 U6.1(IN) U6.3(EN)
VBUSS: C173.1 FB14.1 U6.5(OUT)
VCCIN: C104.2 U3.10(VccIN)
VDDD33: C1.1 C2.1 C41.1 C42.1 C43.1 C172.1 C180.1 C186.1 C187.1 C188.1 C189.1 D1.1(ANODE) D7.1(ANODE) FB12.1 FB13.1 JP6.1(Pin1) R27.1 R28.1 R30.1 R39.1 R41.1 R114.1 R115.1 R123.1 R124.1 R125.1 R130.1 U2.1(V+) U2.10(A1) U7.5(VCC) U8.20(VCCIO) U8.31(VCCIO) U8.42(VCCIO) U8.56(VCCIO) U9.8(VCC) U15.8(V+) ; also on sheet 13 15
VINA: BALUN1.1(IN) J2.1(CENTER)
VINB: BALUN2.1(IN) J5.1(CENTER)
1P8V_USB: C178.1 C179.1 C181.1 C182.1 C183.1 PP16.1 U8.12(VCORE) U8.37(VCORE) U8.49(VREGOUT) U8.64(VCORE)
3P3USB: C170.1 C171.1 FB13.2 PP15.1 U8.9(VPLL)
3P3V_RX: PP18.1 R105.2
3P3VAUX: C167.2 J25.D32 J28.4 U5.8(VCC)
12P0V_RX: J25.C35 J25.C37
ADBUS0: U8.16(ADBUS0) ; also on sheet 13
ADBUS1: U8.17(ADBUS1) ; also on sheet 13
ADBUS2: U8.18(ADBUS2) ; also on sheet 13
ADBUS3: U8.19(ADBUS3) ; also on sheet 13
ADC_CLK: U1.G14(SCLK) ; also on sheet 13
ADC_SCSb: U1.G13(\\~{SCS}) ; also on sheet 13
ADC_SDI: U1.H13(SDI) ; also on sheet 13
ADC_SDO: U1.H14(SDO) ; also on sheet 13
BDBUS0: R112.1 U8.26(BDBUS0)
BDBUS1: U7.2(A) U8.27(BDBUS1)
BDBUS2: R113.1 U8.28(BDBUS2)
BDBUS3: U7.1(~{OE}) U8.29(BDBUS3)
CALTRG: J9.2 R23.1 U1.A9(CALTRG)
CDBUS0: R118.1 U8.38(CDBUS0)
CDBUS1: R119.1 U8.39(CDBUS1)
CDBUS2: R115.2 R120.1 U8.40(CDBUS2)
CDBUS3: R114.2 R121.1 U8.41(CDBUS3)
CE: JP5.2 R46.1 U3.1(CE)
CLK+: C49.1 R43.2 T2.1(secondary_dot)
CLK-: C52.1 R43.1 T2.3(secondary)
CLK-IN: R67.1 R69.1 R70.2 R72.1 T1.6(primary_dot)
CLK_+: C48.2 C49.2 C50.2 U1.G1(CLK+)
CLK_-: C51.2 C52.2 C53.2 U1.H1(CLK-)
CLKIN0: J38.1(CENTER) R186.1 R187.1
CLKIN0_N: C24.2 U4.38(CLKIN0n)
CLKIN0_P: C20.2 U4.37(CLKIN0p)
CLKIN1: C20.1 R186.2
CLKIN1_N: C136.2 C137.2 U4.35(CLKIN1n/FBCLKINn/FINn)
CLKIN1_P: C134.2 U4.34(CLKIN1p/FBCLKINp/FINp)
CLKINN: C136.1 R73.2 T1.3(secondary)
CLKINP: C134.1 R68.1 R69.2 R73.1 T1.1(secondary_dot)
CLKLA_0N: R90.1 R127.1 U4.63(DCLKOUT12n)
CLKLA_0P: R89.1 R126.1 U4.62(DCLKOUT12p)
CLKM: C48.1 C135.2
CLKP: C53.1 C133.2
CP1: C128.1 C130.1 U4.32(CPOUT1) Y1.1(VC)
CP2: C131.1 C132.1 U4.46(CPOUT2)
CPout: C119.1 C120.1 R54.1 U3.12(CPout)
DA0+: C5.1 U1.E14(DA0+)
DA0-: C6.1 U1.F14(DA0-)
DA0_M: C6.2 J25.A11
DA0_P: C5.2 J25.A10
DA1+: C7.1 U1.C14(DA1+)
DA1-: C8.1 U1.D14(DA1-)
DA1_M: C8.2 J25.C7
DA1_P: C7.2 J25.C6
DA2+: C9.1 U1.A12(DA2+)
DA2-: C10.1 U1.A13(DA2-)
DA2_M: C10.2 J25.A7
DA2_P: C9.2 J25.A6
DA3+: C11.1 U1.A10(DA3+)
DA3-: C12.1 U1.A11(DA3-)
DA3_M: C12.2 J25.A3
DA3_P: C11.2 J25.A2
DA4+: C13.1 U1.E13(DA4+)
DA4-: C15.1 U1.F13(DA4-)
DA4_M: C15.2 J25.Y15
DA4_P: C13.2 J25.Y14
DA5+: C16.1 U1.C13(DA5+)
DA5-: C18.1 U1.D13(DA5-)
DA5_M: C18.2 J25.Y11
DA5_P: C16.2 J25.Y10
DA6+: C19.1 U1.B12(DA6+)
DA6-: C21.1 U1.B13(DA6-)
DA6_M: C21.2 J25.B9
DA6_P: C19.2 J25.B8
DA7+: C22.1 U1.B10(DA7+)
DA7-: C23.1 U1.B11(DA7-)
DA7_M: C23.2 J25.B5
DA7_P: C22.2 J25.B4
DB0+: C25.1 U1.K14(DB0+)
DB0-: C26.1 U1.J14(DB0-)
DB0_M: C26.2 J25.B12
DB0_P: C25.2 J25.B13
DB1+: C27.1 U1.M14(DB1+)
DB1-: C28.1 U1.L14(DB1-)
DB1_M: C28.2 J25.A14
DB1_P: C27.2 J25.A15
DB2+: C29.1 U1.P12(DB2+)
DB2-: C30.1 U1.P13(DB2-)
DB2_M: C30.2 J25.B16
DB2_P: C29.2 J25.B17
DB3+: C31.1 U1.P10(DB3+)
DB3-: C32.1 U1.P11(DB3-)
DB3_M: C32.2 J25.A18
DB3_P: C31.2 J25.A19
DB4+: C33.1 U1.K13(DB4+)
DB4-: C34.1 U1.J13(DB4-)
DB4_M: C34.2 J25.Z12
DB4_P: C33.2 J25.Z13
DB5+: C35.1 U1.M13(DB5+)
DB5-: C36.1 U1.L13(DB5-)
DB5_M: C36.2 J25.Z16
DB5_P: C35.2 J25.Z17
DB6+: C37.1 U1.N12(DB6+)
DB6-: C38.1 U1.N13(DB6-)
DB6_M: C38.2 J25.Y18
DB6_P: C37.2 J25.Y19
DB7+: C39.1 U1.N10(DB7+)
DB7-: C40.1 U1.N11(DB7-)
DB7_M: C40.2 J25.Y22
DB7_P: C39.2 J25.Y23
DCLKOUT2_N: C135.1 R75.1 U4.16(DCLKOUT2n)
DCLKOUT2_P: C133.1 R74.1 U4.15(DCLKOUT2p)
DCLKOUT6_N: C153.1 R95.1 U4.28(DCLKOUT6n)
DCLKOUT6_P: C151.1 R94.1 U4.27(DCLKOUT6p)
DCLKOUT8_N: R24.1 R57.1 U4.52(DCLKOUT8n)
DCLKOUT8_P: R22.1 R58.1 U4.51(DCLKOUT8p)
DCLKOUT10_N: C143.2 J24.1(CENTER)
DCLKOUT10_P: C142.2 J23.1(CENTER)
DCLKOUT10N: C143.1 R87.1 U4.55(DCLKOUT10n)
DCLKOUT10P: C142.1 R86.1 U4.54(DCLKOUT10p)
DDBUS0: U8.48(DDBUS0) ; also on sheet 13
DDBUS1: U8.52(DDBUS1) ; also on sheet 13
DDBUS2: U8.53(DDBUS2) ; also on sheet 13
DDBUS3: U8.54(DDBUS3) ; also on sheet 13
DDBUS4: R225.2 U8.55(DDBUS4) ; also on sheet 13
DDBUS5: U8.57(DDBUS5) ; also on sheet 13
DDBUS6: R226.2 U8.58(DDBUS6) ; also on sheet 13
DDBUS7: U8.59(DDBUS7) ; also on sheet 13
DEVCLKIN: J18.1(CENTER) T2.6(primary_dot)
DM: R116.2 U8.7(DM)
DP: R117.2 U8.8(DP)
EE_ADDR0_RX: J25.C34 U5.1(A0)
EE_ADDR1_RX: J25.D35 U5.2(A1)
EECLK: R124.2 U8.62(EECLK) U9.2(CLK)
EECS: R125.2 U8.63(EECS) U9.1(CS)
EEDATA: R131.1 U8.61(EEDATA) U9.3(DI)
FMC_ADC_SCSb: J25.H38 ; also on sheet 13
FMC_ADC_SDI: J25.G36 ; also on sheet 13
FMC_DATA: J25.G37 SJP8.1(Pin1) ; also on sheet 13
FMC_LMK_SCSb: J25.G34 SJP9.1(Pin1)
FMC_LMK_SDI: J25.G24 SJP12.1(Pin1)
FMC_LMX_SCSb: J25.G33 SJP10.1(Pin1)
FMC_LMX_SDI: J25.G21 SJP11.1(Pin1)
FMC_SCL: J25.C30 J28.2 U5.6(SCL)
FMC_SCLK: J25.H37 SJP7.1(Pin1) ; also on sheet 13
FMC_SDA: J25.C31 J28.1 U5.5(SDA)
FPGA_JESD_CLK_A_N: J25.D5 R129.2
FPGA_JESD_CLK_A_P: J25.D4 R128.2
FPGA_JESD_CLK_B_N: J25.G7 R127.2
FPGA_JESD_CLK_B_P: J25.G6 R126.2
FPGA_JESD_CLK_C_N: J25.Z21 R24.2
FPGA_JESD_CLK_C_P: J25.Z20 R22.2
FPGA_JESD_SYSREFM: J25.G10 R60.2
FPGA_JESD_SYSREFP: J25.G9 R59.2
GTXCLKM: R64.1 R129.1 U4.2(DCLKOUT0n)
GTXCLKP: R65.1 R128.1 U4.1(DCLKOUT0p)
HSPC_PRSNT_M2C_L: J25.Z1 J30.1
INA+: BALUN1.3(O1) R1.1
INA-: BALUN1.2(O2) R4.1
INA_+: J1.1(CENTER) R180.1
INA_-: J3.1(CENTER) R179.1
INAN: R4.2 R179.2 U1.A5(INA-)
INAP: R1.2 R180.2 U1.A4(INA+)
INB+: BALUN2.2(O2) R6.1
INB-: BALUN2.3(O1) R9.1
INB_+: J4.1(CENTER) R151.1
INB_-: J6.1(CENTER) R162.1
INBN: R9.2 R162.2 U1.P5(INB-)
INBP: R6.2 R151.2 U1.P4(INB+)
JESD_SYSREFM: R60.1 R61.1 U4.4(SDCLKOUT1n)
JESD_SYSREFP: R59.1 R62.1 U4.3(SDCLKOUT1p)
LMK04828_CSb: SJP9.2(Pin2) TP5.1(TP) U4.18(\\~{CS})
LMK04828_SYNC: J25.J15 R97.2
LMK LOCKED: D5.1(ANODE) R102.1
LMK_CLKIN: J22.1(CENTER) R70.1 R71.1
LMK_LMX_CLK: SJP7.2(Pin2) U3.16(SCK) U4.19(SCK)
LMK_LMX_DATA: SJP8.2(Pin2) U3.17(SDI) U4.20(SDIO)
LMK_SDO: R99.1 SJP12.2(Pin2) U4.5(RESET)
LMX_CLKB: C108.2 R52.2 R67.2
LMX_CLKM: C50.1 R45.1 U3.22(RFoutAM)
LMX_CLKP: C51.1 R44.1 U3.23(RFoutAP)
LMX_CSb: SJP10.2(Pin2) U3.24(CSB)
LMX_OSCM: C151.2 C249.1 U3.9(OSCinM)
LMX_OSCP: C153.2 C250.1 U3.8(OSCinP)
LMX_SDO: R47.2 SJP11.2(Pin2)
MUX_OUT: R47.1 R50.2 U3.20(MUXout)
NCOA0: J7.2 R11.1 U1.A7(NCOA0) ; also on sheet 13
NCOA1: J7.4 R12.1 U1.B7(NCOA1) ; also on sheet 13
NCOB0: J7.6 R17.1 U1.P7(NCOB0) ; also on sheet 13
NCOB1: J7.8 R18.1 U1.N7(NCOB1) ; also on sheet 13
OSC_M: C250.2 R188.1 U4.41(OSCOUTn)
OSC_P: C249.2 R189.1 U4.40(OSCOUTp)
OSCI: C184.1 U8.2(OSCI) Y2.2
OSCINN: C150.2 C152.2 U4.44(OSCINn)
OSCINP: C145.2 C146.2 U4.43(OSCINp)
OSCN: C149.2 C150.1 R88.2 R93.1
OSCO: C185.1 U8.3(OSCO) Y2.1
OSCP: C144.2 C145.1 R82.2 R85.1
OVRA: J25.H28 R225.1
OVRA0: D12.1(ANODE) J25.G27 U1.A8(OVRA0) ; also on sheet 13
OVRA1: U1.B8(OVRA1) ; also on sheet 13
OVRB: J25.H29 R226.1
OVRB0: D9.1(ANODE) J25.D26 U1.P8(OVRB0) ; also on sheet 13
OVRB1: U1.N8(OVRB1) ; also on sheet 13
PD: J8.2 R21.1 U1.P9(PD)
PG_RX1: J25.F1 J26.2 R104.2
PLL2 LOCKED: D6.1(ANODE) R103.1
PRSNT_M2C_L: J25.H2 R106.1
RFOUTB_M: C110.1 R49.1 U3.19(RFoutBM)
RFOUTB_P: C108.1 R48.1 U3.18(RFoutBP)
RFOUTBM: C110.2 J20.1(CENTER) R53.2
STAT 0: D3.1(ANODE) R100.1
STAT 1: D4.1(ANODE) R101.1
SYNC: R96.1 R97.1 R98.1 TP4.1(TP) U4.6(SYNC)
SYNC_N: J25.G13 R36.1
SYNC_P: J25.G12 R35.1
SYNC_SE: J25.H31 R25.1 R98.2
SYNCSE: R25.2 R26.1 U1.B2(SYNC~_SE)
SYS+: C45.2 U1.L1(SYSREF+)
SYS-: C47.2 U1.M1(SYSREF-)
SYSREF+: R76.1 R78.1 U4.13(SDCLKOUT3p)
SYSREF-: R77.1 R79.1 U4.14(SDCLKOUT3n)
SYSREFM: C47.1 R77.2 R80.1
SYSREFP: C45.1 R76.2 R81.1
TCRIT1: R28.2 R37.2 TP1.1(TP) U2.4(\\~{THERM})
TCRIT2: R27.2 TP2.1(TP) U2.7(\\~{ALERT/THERM2})
TDI: J25.D30 J27.1
TDIODE+: J17.2 R40.2 U1.N2(TDIODE+)
TDIODE-: J17.1 R42.2 U1.P2(TDIODE-)
TDIODEN: C44.2 R42.1 U2.3(D-)
TDIODEP: C44.1 R40.1 U2.2(D+)
TDO: J25.D31 J27.2
TMP461_SMBCLK: R41.2 R112.2 U2.9(SCL)
TMP461_SMBDAT: R39.2 R110.2 R113.2 U2.8(SDA)
TMSP+: J14.1(CENTER) R34.1
TMSP-: J15.1(CENTER) R38.1
TMSTP+: R34.2 R35.2 U1.C1(TMSTP+)
TMSTP-: R36.2 R38.2 U1.D1(TMSTP-)
V_BUS: C174.1 C177.1 FB14.2 JP6.3(Pin3)
VA11: C54.1 C55.1 C56.1 C57.1 C58.1 C59.1 C60.1 C61.1 C62.1 C63.1 C66.1 C67.1 C68.1 PP19.1 U1.D3(VA11) U1.E3(VA11) U1.F2(VA11) U1.F3(VA11) U1.G3(VA11) U1.H3(VA11) U1.J2(VA11) U1.J3(VA11) U1.K3(VA11) U1.L3(VA11) ; also on sheet 15
VA19: C69.1 C70.1 C71.1 C72.1 C73.1 C74.1 C75.1 C76.1 C77.1 C78.1 C79.1 C80.1 C81.1 C82.1 C83.1 PP20.1 R13.1 R14.1 R15.1 R16.1 R19.1 R20.1 U1.C2(VA19) U1.C3(VA19) U1.C4(VA19) U1.C5(VA19) U1.D2(VA19) U1.E1(VA19) U1.E2(VA19) U1.K1(VA19) U1.K2(VA19) U1.L2(VA19) U1.M2(VA19) U1.M3(VA19) U1.M4(VA19) U1.M5(VA19) ; also on sheet 14
VADJ_RX: J25.E39 J25.F40 J25.G39 J25.H40 PP17.1 R104.1 R107.1
VBIAS_VCO: C116.2 U3.3(VbiasVCO)
VBIASBANK: C109.1 C111.2 U3.27(VbiasBANK)
VD11: C64.1 C65.1 C84.1 C85.1 C86.1 C87.1 C88.1 C89.1 C90.1 C91.1 C92.1 C93.1 C94.1 C95.1 C96.1 PP21.1 U1.C10(VD11) U1.C11(VD11) U1.C12(VD11) U1.D12(VD11) U1.E12(VD11) U1.F12(VD11) U1.G12(VD11) U1.H12(VD11) U1.J12(VD11) U1.K12(VD11) U1.L12(VD11) U1.M10(VD11) U1.M11(VD11) U1.M12(VD11) ; also on sheet 15
VIO_B_M2C_RX: J25.J39 J25.K40 R107.2
VPHY: C168.1 C169.1 FB12.2 U8.4(VPHY)
VREF_VCO1: C112.2 U3.29(VrefVCO)
VREF_VCO2: C115.2 U3.36(VrefVCO)
VREG_VCO: C117.2 U3.38(VregVCO)
VREGIN: C176.1 JP6.2(Pin2) U8.50(VREGIN)
VTUNE: C122.1 R55.2 U3.35(Vtune)
Y1_N: R91.1 R92.1 Y1.4(OUT_N)
Y1_P: R83.1 R84.1 Y1.5(OUT_P)
YO1_N: C149.1 R91.2
YO1_P: C144.1 R83.2
N19884870: C138.2 C139.2 C140.2 C141.2 FB1.1 Y1.6(VDD)
N19884947: SJP1.2(Pin2) Y1.2(NC)
N19887754: FB8.2 U4.42(VCC8_OSCin)
N19887756: C160.2 C161.2 C162.2 FB6.2 FB7.1 FB8.1 FB9.1 U4.47(VCC10_PLL2)
N19887760: C165.1 FB10.2 U4.53(VCC11_CG3)
N19887762: C166.1 FB11.2 U4.64(VCC12_CG0)
N19887789: R102.2 U4.31(STATUS_LD1)
N19887795: R103.2 U4.48(STATUS_LD2)
N19887804: R101.2 U4.59(CLKin_SEL1)
N19887822: R100.2 U4.58(CLKin_SEL0)
N19887828: C163.1 U4.12(LDObyp2)
N19887830: C164.1 U4.11(LDObyp1)
N19887836: C154.2 C155.2 C156.2 FB2.2 U4.10(VCC1_VCO) U4.33(VCC5_DIG) U4.36(VCC6_PLL1)
N19887876: FB7.2 U4.39(VCC7_OSCout)
N19887878: FB9.2 U4.45(VCC9_CP2)
N19887910: C158.1 FB4.2 U4.21(VCC3_SYSREF)
N19887912: C157.1 FB3.2 U4.17(VCC2_CG1)
N19887930: C159.1 FB5.2 U4.26(VCC4_CG2)
N20234062: C118.2 U3.33(VbiasVARAC)
N20239082: R51.2 U3.30(Rext)
N20251064: C120.2 R56.1
N20251377: C121.1 R54.2 R55.1
N20258125: D2.1(ANODE) R50.1
N20381922: R130.2 U8.14(RESET)
N20381931: R122.2 U8.6(REF)
N20382558: R123.2 R131.2 U9.4(DO)
N20382827: J31.3(D+) R117.1
N20382847: J31.2(D-) R116.1
N20392160: J31.1(VBUS) R111.2
N20393078: D7.2(CATHODE) R109.1
N20442573: J7.1 R13.2
N20442576: J7.3 R14.2
N20442579: J7.5 R15.2
N20442582: J7.7 R16.2
N20446174: TP9.1(TP) U1.A2(BG)
N20447902: D1.2(CATHODE) R37.1
N20478124: R110.1 U7.4(Y)
N20523656: TP10.1(TP) U1.B9(CALSTAT)
N20560674: J25.C39 J25.D36 J25.D38 J25.D40 R105.1
N20560927: J25.D1 J26.1
N20597236: J30.2 R108.1
N20601243: D10.1(ANODE) U15.7(OUTB)
N20601382: D11.1(ANODE) U15.1(OUTA)
N20601403: D10.2(CATHODE) R185.1
N20601859: D11.2(CATHODE) R32.1
N20602433: C14.2 D9.2(CATHODE) R184.1 U15.5(INB+)
N20603216: C3.2 D12.2(CATHODE) R31.1 U15.3(INA+)
N20603624: C4.2 R30.2 R33.1 U15.2(INA-) U15.6(INB-)
N20606076: J9.1 R20.2
N20606250: J8.1 R19.2
N20809211: R178.1 U8.44(CDBUS5)
N20837548: R118.2 SJP7.3(Pin3)
N20837573: R119.2 SJP8.3(Pin3)
N20837587: R120.2 SJP9.3(Pin3)
N20837623: R121.2 SJP10.3(Pin3)
N20837793: SJP11.3(Pin3) U8.43(CDBUS4)
N20837816: R178.2 SJP12.3(Pin3)
N21029365: C131.2 R66.1
N21029367: C128.2 R63.1

Not connected (* = marked no-connect by the designer): J25 A22 A23 A26 A27 A30 A31 A34 A35 A38 A39 B1 B2 B19 B20* B21* B24 B25 B28 B29 B32 B33 B36 B37 B40 C2 C3 C4 C10 C11 C12 C13 C14 C15 C16 C17 C18 C19 C20 C22* C23* C26* C27* D2 D8* D9* D10 D11 D12 D13 D14 D15 D16 D17 D18 D19 D20* D21* D22 D23 D24* D27 D29* D33* D34 E1 E2 E3 E4 E5 E6 E7 E8 E9 E10 E11 E12 E13 E14 E15 E16 E17 E18 E19 E20 E21 E22 E23 E24 E25 E27 E28 E30 E31 E33 E34 E36 E37 F2 F3 F4 F5 F6 F7 F8 F10 F11 F12 F13 F14 F15 F16 F17 F18 F19 F20 F21 F22 F23 F24 F25 F26 F28 F29 F31 F32 F34 F35 F37 F38 G1 G2 G3 G4 G15 G16 G17 G18 G19 G20 G22 G23 G25 G28 G30 G31 H1 H3 H4 H5 H6 H7 H8 H9 H10 H11 H12 H13 H14 H15 H16 H17 H18 H19 H20 H21 H22 H23 H24 H25 H26 H32 H34 H35 J1 J2 J3 J4 J5 J6 J7 J8 J9 J10 J11 J12 J13 J14 J16 J17 J18 J19 J20 J21 J22 J23 J24 J25 J27 J28 J30 J31 J33 J34 J36 J37 K1 K2 K3 K4 K5 K6 K7 K8 K9 K10 K11 K12 K13 K14 K15 K16 K17 K18 K19 K20 K21 K22 K23 K24 K25 K26 K28 K29 K31 K32 K34 K35 K37 K38 L1 L2 L3 L4 L5 L6 L7 L8 L9 L10 L11 L12 L13 L14 L15 L16 L17 L18 L19 L20 L21 L22 L23 L24 L25 L26 L27 L28 L29 L32 L33 L36 L37 L40 M1 M2 M3 M4 M5 M6 M7 M8 M9 M10 M11 M12 M13 M14 M15 M16 M17 M18 M19 M20 M21 M22 M23 M24 M25 M26 M27 M30 M31 M34 M35 M38 M39 Y1 Y2 Y3 Y6 Y7 Y26 Y27 Y30 Y31 Y34 Y35 Y38 Y39 Z4 Z5 Z8 Z9 Z24 Z25 Z28 Z29 Z32 Z33 Z36 Z37 Z40; J31 4(ID)*; T2 2(NOTUSED)*; U3 5(NC1)* 28(NC2)* 32(NC3)*; U4 7(NC1)* 8(NC2)* 9(NC3)* 22(SDCLKOUT5p)* 23(SDCLKOUT5n)* 24(DCLKOUT4p)* 25(DCLKOUT4n)* 29(SDCLKOUT7p)* 30(SDCLKOUT7n)* 49(SDCLKOUT9p)* 50(SDCLKOUT9n)* 56(SDCLKOUT11p)* 57(SDCLKOUT11n)* 60(SDCLKOUT13p)* 61(SDCLKOUT13n)*; U8 21(ADBUS4)* 22(ADBUS5)* 23(ADBUS6)* 24(ADBUS7)* 30(BDBUS4)* 32(BDBUS5)* 33(BDBUS6)* 34(BDBUS7)* 36(SUSPEND)* 45(CDBUS6)* 46(CDBUS7)* 60(PWREN)*; U9 6(ORG)*

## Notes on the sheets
sheet 1
- MECHANICAL PARTS
sheet 2
- POWER
- USB
- SUPPLIES
- LEVEL SHIFTERS
- PAGES 13, 14
- PAGES  11, 12
- SPI
- JESD204B DATA
- FMC
- ANALOG INPUT
    CHANNEL A
- CONNECTOR
- ADC12DJ3200EVMCVAL
- SYNCB
- PAGE 2
- PAGES 8, 9, 10
- PAGES 2, 3, 4
- SPI
- ANALOG INPUT
    CHANNEL B
- PAGE 2
- CLK
- SYSREF
- SPI
- SYSREF
- EXT CLK
- LMK04828
- PAGES 6, 7
- LMKCLK
- LMXCLK
- LMX2582
- PAGE 5
- 12500 TI Boulevard. Dallas, Texas 75243
- Engineer:
- J BRINKHURST  11/2016
- PCB:
- JV SMITH  11/2016
sheet 3
- R1 & R180 share a pad.
- Only the P and M's need to match.
- R4 & R179 share a pad.
- R6 & R151 share a pad.
- R9 & R162 share a pad.
- 12500 TI Boulevard. Dallas, Texas 75243
sheet 4
- R34 & R35 Share a pad.
- R36 & R38 share a pad.
- C48, C49, C50 share a pad.
- C51, C52, C53 share a pad.
- 12500 TI Boulevard. Dallas, Texas 75243
sheet 6
- RFOUTBP
- 12500 TI Boulevard. Dallas, Texas 75243
sheet 7
- FPGA_JESD*
- MUST MATCH LENGTH.
- Place near Vc pin of Y1
  R20 and C31 form voltage divider
  set the center frequency voltage for PLL2 reference
- Place close to U4
- FPGA_JESD*
- MUST MATCH LENGTH.
- Place close to LMK
- Place close to LMK
- MATCHED LENGTH
- Shared Pad
- Place close to LMK
- FPGA_JESD*
- MUST MATCH LENGTH.
- Y1 CMOS version OUTPUT on PIN 4
- Shared Pad
- Shared Pad
